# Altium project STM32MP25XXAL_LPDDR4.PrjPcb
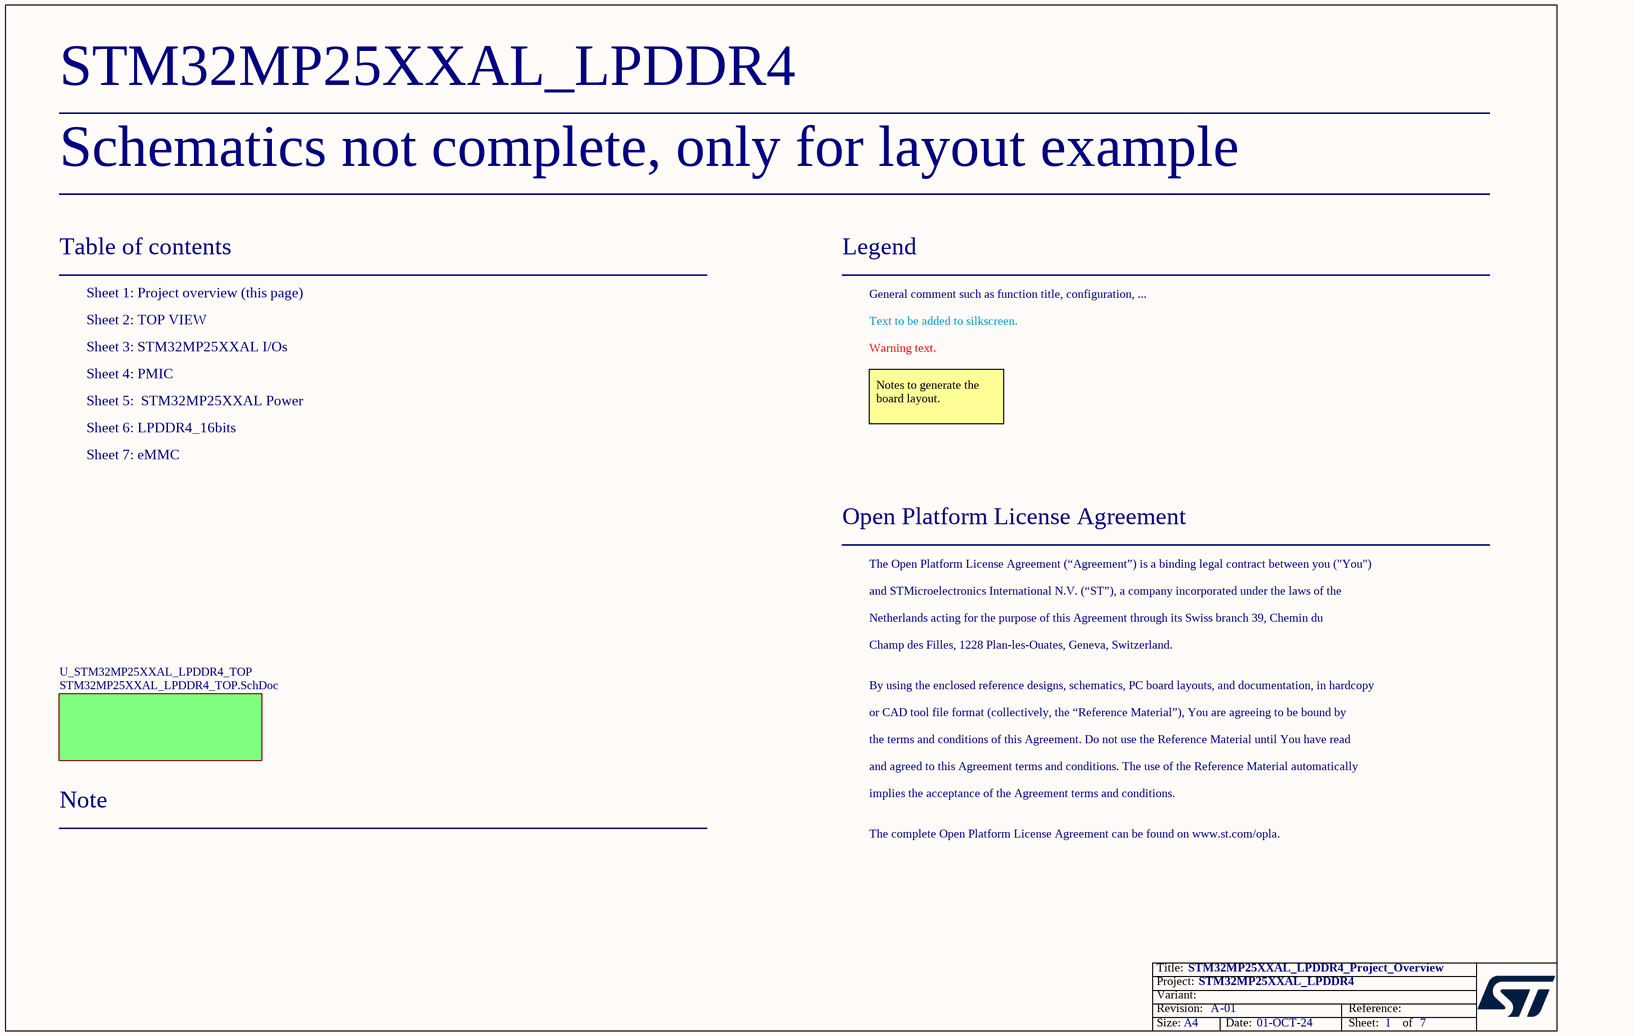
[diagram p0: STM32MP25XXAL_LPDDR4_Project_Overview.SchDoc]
Board_Assembly_Revision: 01; Board_Document_Date: 01-OCT-24; Board_Name: STM32MP25XXAL_LPDDR4; Board_PCB_Revision: A
7 sheets, 182 parts. Net scope: flat (ports and power ports of the same name join across sheets).
Board file: STM32MP25XXAL_LPDDR4.PcbDoc
Sheets:
  STM32MP25XXAL_LPDDR4_Project_Overview.SchDoc
    U_STM32MP25XXAL_LPDDR4_TOP = STM32MP25XXAL_LPDDR4_TOP.SchDoc
      U_STM32MP25XXAL I_Os = STM32MP25XXAL I_Os.SchDoc
      U_PMIC = PMIC.SchDoc
      U_STM32MP25XXAL Power = STM32MP25XXAL Power.SchDoc
      U_eMMC = eMMC.SchDoc
      U_LPDDR4_16bits = LPDDR4_16bits.SchDoc

## Sheet STM32MP25XXAL_LPDDR4_Project_Overview.SchDoc: STM32MP25XXAL_LPDDR4_Project_Overview
size A4; Date: Not used; ApprovedBy: Not used; CheckedBy: Not used; Author: Not used; CompanyName: STMicroelectronics; DrawnBy: Not used; Engineer: Not used; Organization: Not used; Address1: Not used; Address2: Not used; Address3: Not used; Address4: Not used; DocumentNumber: 1; Revision: Not used; SheetNumber: 1; SheetTotal: 7

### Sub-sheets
U_STM32MP25XXAL_LPDDR4_TOP = STM32MP25XXAL_LPDDR4_TOP.SchDoc: no entries

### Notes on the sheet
- Schematics not complete, only for layout example
- Table of contents
- Sheet 1: Project overview (this page)
- Legend
- General comment such as function title, configuration, ...
- Sheet 2: TOP VIEW
- Sheet 3: STM32MP25XXAL I/Os
- Sheet 4: PMIC
- Text to be added to silkscreen.
- Warning text.
- Sheet 5:  STM32MP25XXAL Power
- Sheet 6: LPDDR4_16bits
- Notes to generate the board layout.
- Sheet 7: eMMC
- Open Platform License Agreement
- The Open Platform License Agreement (“Agreement”) is a binding legal contract between you ("You")
- and STMicroelectronics International N.V. (“ST”), a company incorporated under the laws of the
- Netherlands acting for the purpose of this Agreement through its Swiss branch 39, Chemin du
- Champ des Filles, 1228 Plan-les-Ouates, Geneva, Switzerland.
- By using the enclosed reference designs, schematics, PC board layouts, and documentation, in hardcopy
- or CAD tool file format (collectively, the “Reference Material”), You are agreeing to be bound by
- the terms and conditions of this Agreement. Do not use the Reference Material until You have read
- and agreed to this Agreement terms and conditions. The use of the Reference Material automatically
- Note
- implies the acceptance of the Agreement terms and conditions.
- The complete Open Platform License Agreement can be found on www.st.com/opla.

## Sheet STM32MP25XXAL_LPDDR4_TOP.SchDoc: TOP
size A4; Date: Not used; ApprovedBy: Not used; CheckedBy: Not used; Author: Not used; CompanyName: STMicroelectronics; DrawnBy: Not used; Engineer: Not used; Organization: Not used; Address1: Not used; Address2: Not used; Address3: Not used; Address4: Not used; DocumentNumber: 2; Revision: Not used; SheetNumber: 2; SheetTotal: 7
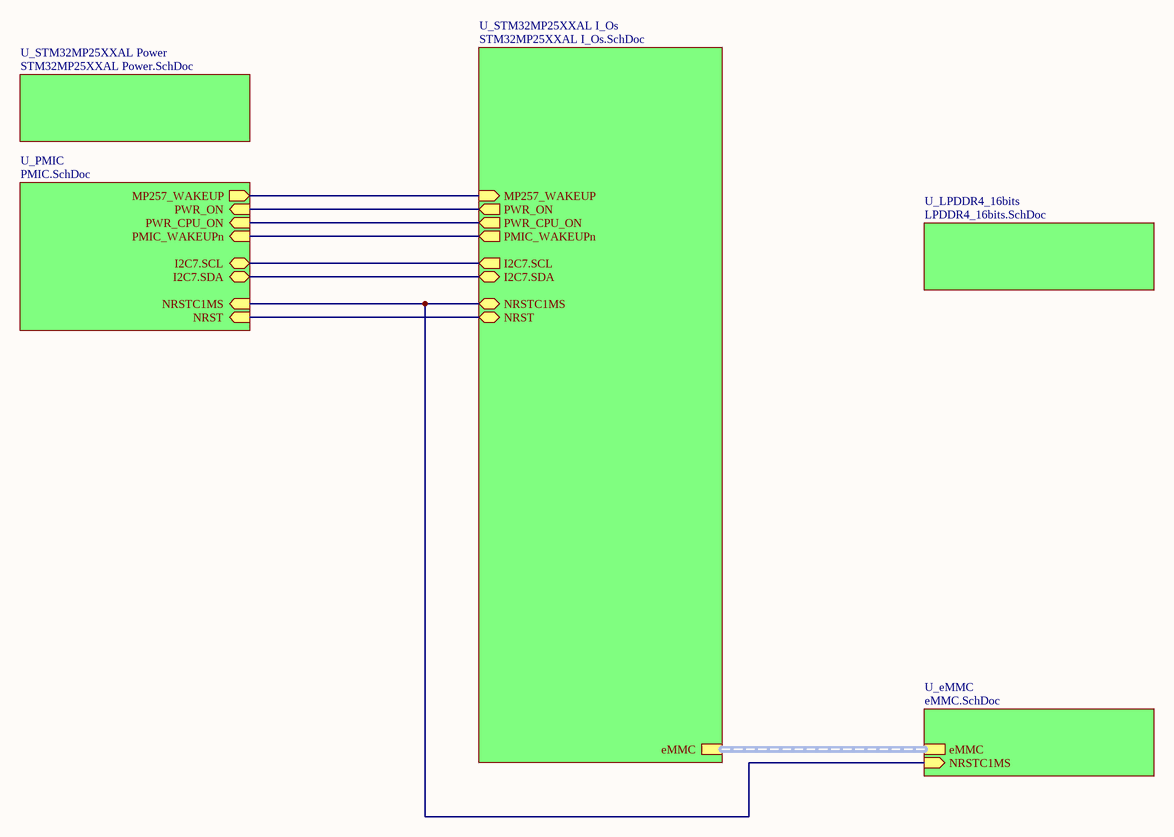
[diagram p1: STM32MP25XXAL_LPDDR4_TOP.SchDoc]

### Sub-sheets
U_eMMC = eMMC.SchDoc: eMMC (harness eMMC), NRSTC1MS (in)
U_LPDDR4_16bits = LPDDR4_16bits.SchDoc: no entries
U_PMIC = PMIC.SchDoc: PMIC_WAKEUPn (in), NRST (in), I2C7.SCL (bidir), PWR_ON (in), PWR_CPU_ON (in), NRSTC1MS (in), I2C7.SDA (bidir), MP257_WAKEUP (out)
U_STM32MP25XXAL I_Os = STM32MP25XXAL I_Os.SchDoc: NRST (bidir), PWR_ON (out), NRSTC1MS (bidir), I2C7.SDA (bidir), I2C7.SCL (out), PWR_CPU_ON (out), MP257_WAKEUP (in), PMIC_WAKEUPn (out), eMMC (harness eMMC)
U_STM32MP25XXAL Power = STM32MP25XXAL Power.SchDoc: no entries

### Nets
(unnamed): sheet U_STM32MP25XXAL I_Os/NRST, sheet U_PMIC/NRST
(unnamed): sheet U_STM32MP25XXAL I_Os/PWR_ON, sheet U_PMIC/PWR_ON  [a separate net that carries the same name]
(unnamed): sheet U_STM32MP25XXAL I_Os/NRSTC1MS, sheet U_PMIC/NRSTC1MS, sheet U_eMMC/NRSTC1MS  [a separate net that carries the same name]
(unnamed): sheet U_STM32MP25XXAL I_Os/I2C7.SDA, sheet U_PMIC/I2C7.SDA  [a separate net that carries the same name]
(unnamed): sheet U_STM32MP25XXAL I_Os/I2C7.SCL, sheet U_PMIC/I2C7.SCL  [a separate net that carries the same name]
(unnamed): sheet U_STM32MP25XXAL I_Os/PWR_CPU_ON, sheet U_PMIC/PWR_CPU_ON  [a separate net that carries the same name]
(unnamed): sheet U_STM32MP25XXAL I_Os/MP257_WAKEUP, sheet U_PMIC/MP257_WAKEUP  [a separate net that carries the same name]
(unnamed): sheet U_STM32MP25XXAL I_Os/PMIC_WAKEUPn, sheet U_PMIC/PMIC_WAKEUPn  [a separate net that carries the same name]

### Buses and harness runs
harness sheet U_eMMC/eMMC = sheet U_STM32MP25XXAL I_Os/eMMC

## Sheet STM32MP25XXAL I_Os.SchDoc: STM32MP25XXAL  I/Os
size A3; Date: Not used; ApprovedBy: Not used; CheckedBy: Not used; Author: Not used; CompanyName: STMicroelectronics; DrawnBy: Not used; Engineer: Not used; Organization: Not used; Address1: Not used; Address2: Not used; Address3: Not used; Address4: Not used; DocumentNumber: 3; Revision: Not used; SheetNumber: 3; SheetTotal: 7
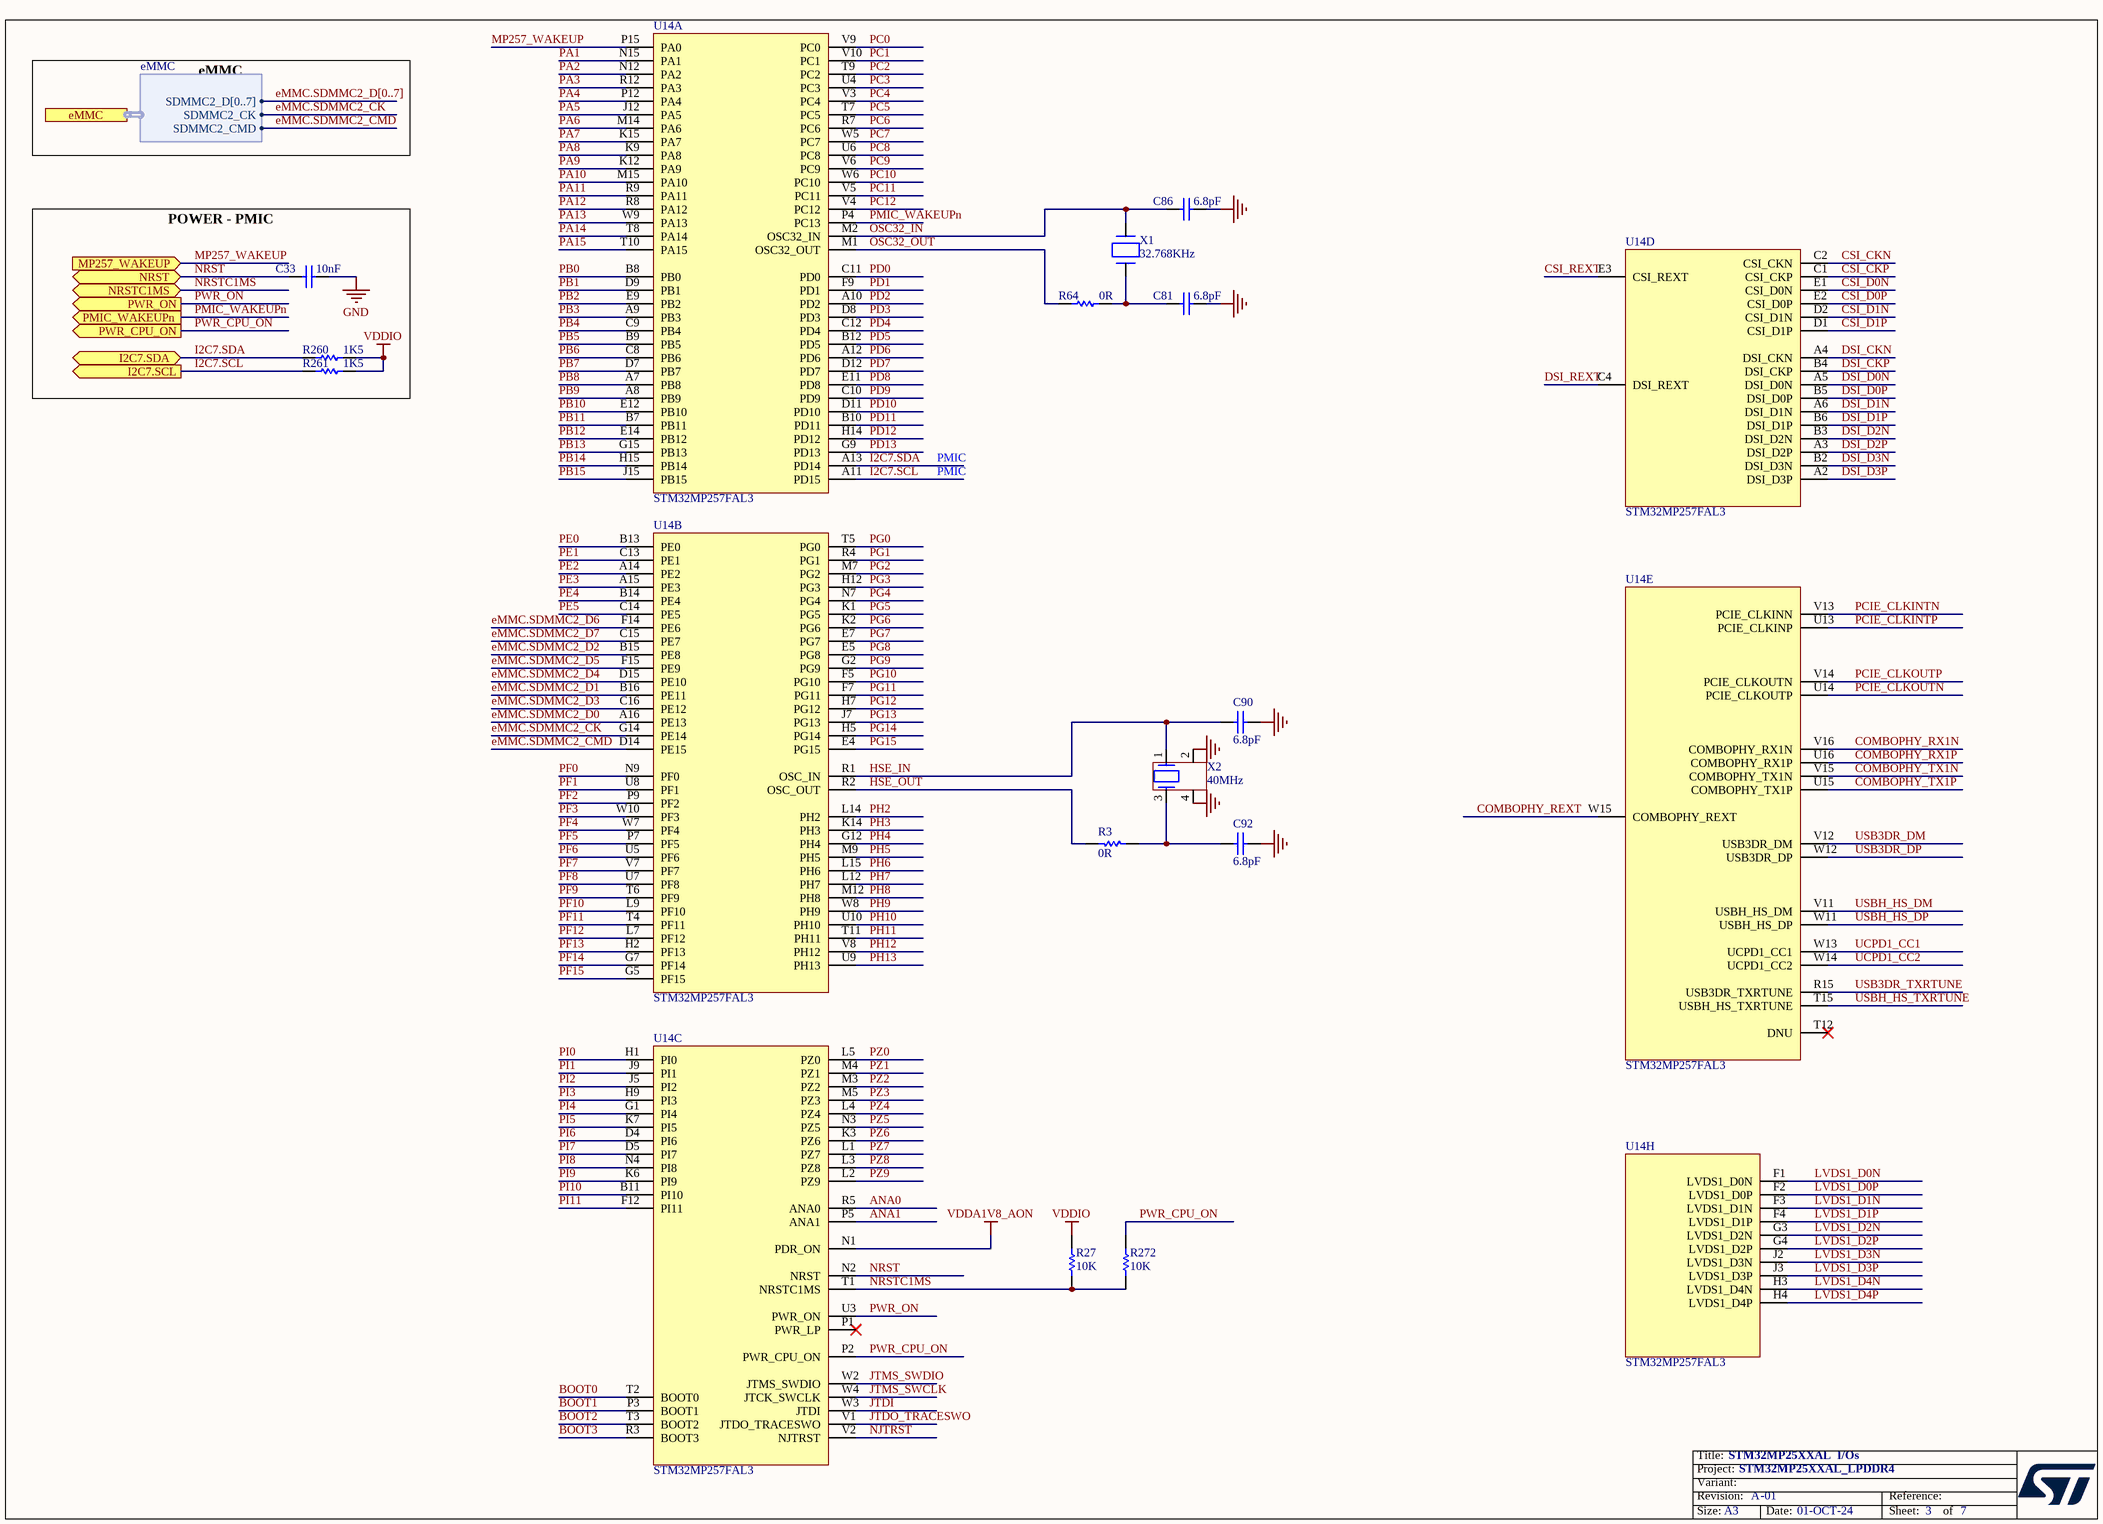
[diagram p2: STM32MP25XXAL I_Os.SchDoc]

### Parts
C33  value 10nF  [C0402]  (hidden comment: Capacitor)
C81  value 6.8pF  [C0402]  (hidden comment: Capacitor)
C86  value 6.8pF  [C0402]  (hidden comment: Capacitor)
C90  value 6.8pF  [C0402]  (hidden comment: Capacitor)
C92  value 6.8pF  [C0402]  (hidden comment: Capacitor)
R3  value 0R  [R0402]  (hidden comment: Resistor)
R27  value 10K  [R0402]  (hidden comment: Resistor)
R64  value 0R  [R0402]  (hidden comment: Resistor)
R260  value 1K5  [R0402]  (hidden comment: Resistor)
R261  value 1K5  [R0402]  (hidden comment: Resistor)
R272  value 10K  [R0402]  (hidden comment: Resistor)
U14  STM32MP257FAL3  [ICC_VFBGA361_10X10_P050]  (parts A,B,C,D,E,H of 8)
X1  value 32.768KHz  [CRY_NX2012SA_2P]  (hidden comment: XTAL_2_PINS)
X2  value 40MHz  [CRY_NX1612SA_4P]  (hidden comment: XTAL_4_PINS)

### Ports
eMMC (harness eMMC), I2C7.SCL (out), I2C7.SDA (bidir), MP257_WAKEUP (in), NRST (bidir), NRSTC1MS (bidir), PMIC_WAKEUPn (out), PWR_CPU_ON (out), PWR_ON (out)

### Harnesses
eMMC: SDMMC2_CK, SDMMC2_CMD, SDMMC2_D[0..7]

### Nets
GND: C33.1 C81.2 C86.2 C90.1 C92.2 X2.2 X2.4
VDDA1V8_AON: U14.N1(PDR_ON)
VDDIO: R27.2 R260.2 R261.2
ANA0: U14.R5(ANA0)
ANA1: U14.P5(ANA1)
BOOT0: U14.T2(BOOT0)
BOOT1: U14.P3(BOOT1)
BOOT2: U14.T3(BOOT2)
BOOT3: U14.R3(BOOT3)
COMBOPHY_REXT: U14.W15(COMBOPHY_REXT)
COMBOPHY_RX1N: U14.V16(COMBOPHY_RX1N)
COMBOPHY_RX1P: U14.U16(COMBOPHY_RX1P)
COMBOPHY_TX1N: U14.V15(COMBOPHY_TX1N)
COMBOPHY_TX1P: U14.U15(COMBOPHY_TX1P)
CSI_CKN: U14.C2(CSI_CKN)
CSI_CKP: U14.C1(CSI_CKP)
CSI_D0N: U14.E1(CSI_D0N)
CSI_D0P: U14.E2(CSI_D0P)
CSI_D1N: U14.D2(CSI_D1N)
CSI_D1P: U14.D1(CSI_D1P)
CSI_REXT: U14.E3(CSI_REXT)
DSI_CKN: U14.A4(DSI_CKN)
DSI_CKP: U14.B4(DSI_CKP)
DSI_D0N: U14.A5(DSI_D0N)
DSI_D0P: U14.B5(DSI_D0P)
DSI_D1N: U14.A6(DSI_D1N)
DSI_D1P: U14.B6(DSI_D1P)
DSI_D2N: U14.B3(DSI_D2N)
DSI_D2P: U14.A3(DSI_D2P)
DSI_D3N: U14.B2(DSI_D3N)
DSI_D3P: U14.A2(DSI_D3P)
DSI_REXT: U14.C4(DSI_REXT)
eMMC.SDMMC2_CK: U14.G14(PE14) ; port eMMC.SDMMC2_CK
eMMC.SDMMC2_CMD: U14.D14(PE15) ; port eMMC.SDMMC2_CMD
eMMC.SDMMC2_D0: U14.A16(PE13)
eMMC.SDMMC2_D1: U14.B16(PE11)
eMMC.SDMMC2_D2: U14.B15(PE8)
eMMC.SDMMC2_D3: U14.C16(PE12)
eMMC.SDMMC2_D4: U14.D15(PE10)
eMMC.SDMMC2_D5: U14.F15(PE9)
eMMC.SDMMC2_D6: U14.F14(PE6)
eMMC.SDMMC2_D7: U14.C15(PE7)
HSE_IN: C90.2 U14.R1(OSC_IN) X2.1
HSE_OUT: R3.2 U14.R2(OSC_OUT)
I2C7.SCL: R261.1 U14.A11(PD15) ; port I2C7.SCL
I2C7.SDA: R260.1 U14.A13(PD14) ; port I2C7.SDA
JTDI: U14.W3(JTDI)
JTDO_TRACESWO: U14.V1(JTDO_TRACESWO)
JTMS_SWCLK: U14.W4(JTCK_SWCLK)
JTMS_SWDIO: U14.W2(JTMS_SWDIO)
LVDS1_D0N: U14.F1(LVDS1_D0N)
LVDS1_D0P: U14.F2(LVDS1_D0P)
LVDS1_D1N: U14.F3(LVDS1_D1N)
LVDS1_D1P: U14.F4(LVDS1_D1P)
LVDS1_D2N: U14.G3(LVDS1_D2N)
LVDS1_D2P: U14.G4(LVDS1_D2P)
LVDS1_D3N: U14.J2(LVDS1_D3N)
LVDS1_D3P: U14.J3(LVDS1_D3P)
LVDS1_D4N: U14.H3(LVDS1_D4N)
LVDS1_D4P: U14.H4(LVDS1_D4P)
MP257_WAKEUP: U14.P15(PA0) ; port MP257_WAKEUP
NJTRST: U14.V2(NJTRST)
NRST: C33.2 U14.N2(NRST) ; port NRST
NRSTC1MS: R27.1 R272.1 U14.T1(NRSTC1MS) ; port NRSTC1MS
OSC32_IN: C86.1 U14.M2(OSC32_IN) X1.2(X2)
OSC32_OUT: R64.1 U14.M1(OSC32_OUT)
PA1: U14.N15(PA1)
PA2: U14.N12(PA2)
PA3: U14.R12(PA3)
PA4: U14.P12(PA4)
PA5: U14.J12(PA5)
PA6: U14.M14(PA6)
PA7: U14.K15(PA7)
PA8: U14.K9(PA8)
PA9: U14.K12(PA9)
PA10: U14.M15(PA10)
PA11: U14.R9(PA11)
PA12: U14.R8(PA12)
PA13: U14.W9(PA13)
PA14: U14.T8(PA14)
PA15: U14.T10(PA15)
PB0: U14.B8(PB0)
PB1: U14.D9(PB1)
PB2: U14.E9(PB2)
PB3: U14.A9(PB3)
PB4: U14.C9(PB4)
PB5: U14.B9(PB5)
PB6: U14.C8(PB6)
PB7: U14.D7(PB7)
PB8: U14.A7(PB8)
PB9: U14.A8(PB9)
PB10: U14.E12(PB10)
PB11: U14.B7(PB11)
PB12: U14.E14(PB12)
PB13: U14.G15(PB13)
PB14: U14.H15(PB14)
PB15: U14.J15(PB15)
PC0: U14.V9(PC0)
PC1: U14.V10(PC1)
PC2: U14.T9(PC2)
PC3: U14.U4(PC3)
PC4: U14.V3(PC4)
PC5: U14.T7(PC5)
PC6: U14.R7(PC6)
PC7: U14.W5(PC7)
PC8: U14.U6(PC8)
PC9: U14.V6(PC9)
PC10: U14.W6(PC10)
PC11: U14.V5(PC11)
PC12: U14.V4(PC12)
PCIE_CLKINTN: U14.V13(PCIE_CLKINN)
PCIE_CLKINTP: U14.U13(PCIE_CLKINP)
PCIE_CLKOUTN: U14.U14(PCIE_CLKOUTP)
PCIE_CLKOUTP: U14.V14(PCIE_CLKOUTN)
PD0: U14.C11(PD0)
PD1: U14.F9(PD1)
PD2: U14.A10(PD2)
PD3: U14.D8(PD3)
PD4: U14.C12(PD4)
PD5: U14.B12(PD5)
PD6: U14.A12(PD6)
PD7: U14.D12(PD7)
PD8: U14.E11(PD8)
PD9: U14.C10(PD9)
PD10: U14.D11(PD10)
PD11: U14.B10(PD11)
PD12: U14.H14(PD12)
PD13: U14.G9(PD13)
PE0: U14.B13(PE0)
PE1: U14.C13(PE1)
PE2: U14.A14(PE2)
PE3: U14.A15(PE3)
PE4: U14.B14(PE4)
PE5: U14.C14(PE5)
PF0: U14.N9(PF0)
PF1: U14.U8(PF1)
PF2: U14.P9(PF2)
PF3: U14.W10(PF3)
PF4: U14.W7(PF4)
PF5: U14.P7(PF5)
PF6: U14.U5(PF6)
PF7: U14.V7(PF7)
PF8: U14.U7(PF8)
PF9: U14.T6(PF9)
PF10: U14.L9(PF10)
PF11: U14.T4(PF11)
PF12: U14.L7(PF12)
PF13: U14.H2(PF13)
PF14: U14.G7(PF14)
PF15: U14.G5(PF15)
PG0: U14.T5(PG0)
PG1: U14.R4(PG1)
PG2: U14.M7(PG2)
PG3: U14.H12(PG3)
PG4: U14.N7(PG4)
PG5: U14.K1(PG5)
PG6: U14.K2(PG6)
PG7: U14.E7(PG7)
PG8: U14.E5(PG8)
PG9: U14.G2(PG9)
PG10: U14.F5(PG10)
PG11: U14.F7(PG11)
PG12: U14.H7(PG12)
PG13: U14.J7(PG13)
PG14: U14.H5(PG14)
PG15: U14.E4(PG15)
PH2: U14.L14(PH2)
PH3: U14.K14(PH3)
PH4: U14.G12(PH4)
PH5: U14.M9(PH5)
PH6: U14.L15(PH6)
PH7: U14.L12(PH7)
PH8: U14.M12(PH8)
PH9: U14.W8(PH9)
PH10: U14.U10(PH10)
PH11: U14.T11(PH11)
PH12: U14.V8(PH12)
PH13: U14.U9(PH13)
PI0: U14.H1(PI0)
PI1: U14.J9(PI1)
PI2: U14.J5(PI2)
PI3: U14.H9(PI3)
PI4: U14.G1(PI4)
PI5: U14.K7(PI5)
PI6: U14.D4(PI6)
PI7: U14.D5(PI7)
PI8: U14.N4(PI8)
PI9: U14.K6(PI9)
PI10: U14.B11(PI10)
PI11: U14.F12(PI11)
PMIC_WAKEUPn: U14.P4(PC13) ; port PMIC_WAKEUPn
PWR_CPU_ON: R272.2 U14.P2(PWR_CPU_ON) ; port PWR_CPU_ON
PWR_ON: U14.U3(PWR_ON) ; port PWR_ON
PZ0: U14.L5(PZ0)
PZ1: U14.M4(PZ1)
PZ2: U14.M3(PZ2)
PZ3: U14.M5(PZ3)
PZ4: U14.L4(PZ4)
PZ5: U14.N3(PZ5)
PZ6: U14.K3(PZ6)
PZ7: U14.L1(PZ7)
PZ8: U14.L3(PZ8)
PZ9: U14.L2(PZ9)
UCPD1_CC1: U14.W13(UCPD1_CC1)
UCPD1_CC2: U14.W14(UCPD1_CC2)
USB3DR_DM: U14.V12(USB3DR_DM)
USB3DR_DP: U14.W12(USB3DR_DP)
USB3DR_TXRTUNE: U14.R15(USB3DR_TXRTUNE)
USBH_HS_DM: U14.V11(USBH_HS_DM)
USBH_HS_DP: U14.W11(USBH_HS_DP)
USBH_HS_TXRTUNE: U14.T15(USBH_HS_TXRTUNE)
NetC81_1: C81.1 R64.2 X1.1(X1)
NetC92_1: C92.1 R3.1 X2.3

Not connected (* = marked no-connect by the designer): U14 P1(PWR_LP)* T12(DNU)*

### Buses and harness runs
bus eMMC.SDMMC2_D[0..7]

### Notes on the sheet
- eMMC
- POWER - PMIC
- PMIC

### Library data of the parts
C33 = MCD-00011: Capacitor, MLCC, 10nF, 16V, X7R, +/-10%, 0402, T=0.5mm; Manufacturer_Part_Number: CC0402KRX7R7BB103; Manufacturer: YAGEO; Part_Preference: Recommended; Order_Code_RS: 3019275; Component_Country_Of_Origin: China; ShowFields: YES; ID: 2469
C81 C86 C90 C92 = MCD-00674: Capacitor, MLCC, 6.8pF, 50V, NPO, +/-0.25pF, 0402, T=0.5mm; Manufacturer_Part_Number: CC0402CRNPO9BN6R8; Manufacturer: YAGEO; Part_Preference: Recommended; Component_Country_Of_Origin: China; ID: 3068; ShowFields: YES
R3 R64 = MCD-00052: Resistor, 0R, 0402, +/-5%, 1/16W; Manufacturer_Part_Number: RC0402JR-070RL; Manufacturer: YAGEO; Part_Preference: Recommended; Order_Code_RS: 9232516RL; Component_Country_Of_Origin: China; ID: 2540; ShowFields: YES
R27 R272 = MCD-00053: Resistor, 10K, 0402, +/-1%, 1/16W; BMS_Part_Number: 9131590; Part_Preference: Recommended; Manufacturer: YAGEO; Manufacturer_Part_Number: RC0402FR-0710KL; Order_Code_RS: 9239359; Component_Country_Of_Origin: China; ID: 2539; ShowFields: YES
R260 R261 = MCD-00068: Resistor, 1K5, 0402, +/-1%, 1/16W; Part_Preference: Recommended; Manufacturer: YAGEO; Manufacturer_Part_Number: RC0402FR-071K5L; Order_Code_RS: 9239251; Component_Country_Of_Origin: China; ID: 2524; ShowFields: YES
U14 = MCD-03768: MPU, dual core ARM cortex-A35 64-bit + M33 32-bit, 808KB SRAM, With Crypto; Part_Type: IC; Part_Preference: Recommended; Manufacturer: STMICROELECTRONICS; Component_Country_Of_Origin: Unknown; ShowFields: YES; ID: 5884
X1 = MCD-01479: Crystal, 32.768kHz, 6pF, +/-20ppm, 80K, 2.05x1.2mm; BMS_Part_Number: 9157049; Part_Type: Crystal_Osc; Part_Preference: Recommended; Manufacturer: NDK; Manufacturer_Part_Number: NX2012SA-32.768KHZ-EXS00A-MU00527; Component_Country_Of_Origin: Unknown; ShowFields: YES; ID: 3579
X2 = MCD-02344: Crystal, 40MHz, 6pF, +/-20ppm, 80R, 1.6x1.2mm; Part_Type: Crystal_Osc; Part_Preference: Not recommended; Manufacturer: NDK; Manufacturer_Part_Number: NX1612SA-40MHZ-EXS00A-CS13836; Component_Country_Of_Origin: Unknown; ShowFields: YES; ID: 4450

## Sheet PMIC.SchDoc: PMIC
size A3; Date: Not used; ApprovedBy: Not used; CheckedBy: Not used; Author: Not used; CompanyName: STMicroelectronics; DrawnBy: Not used; Engineer: Not used; Organization: Not used; Address1: Not used; Address2: Not used; Address3: Not used; Address4: Not used; DocumentNumber: 4; Revision: Not used; SheetNumber: 4; SheetTotal: 7
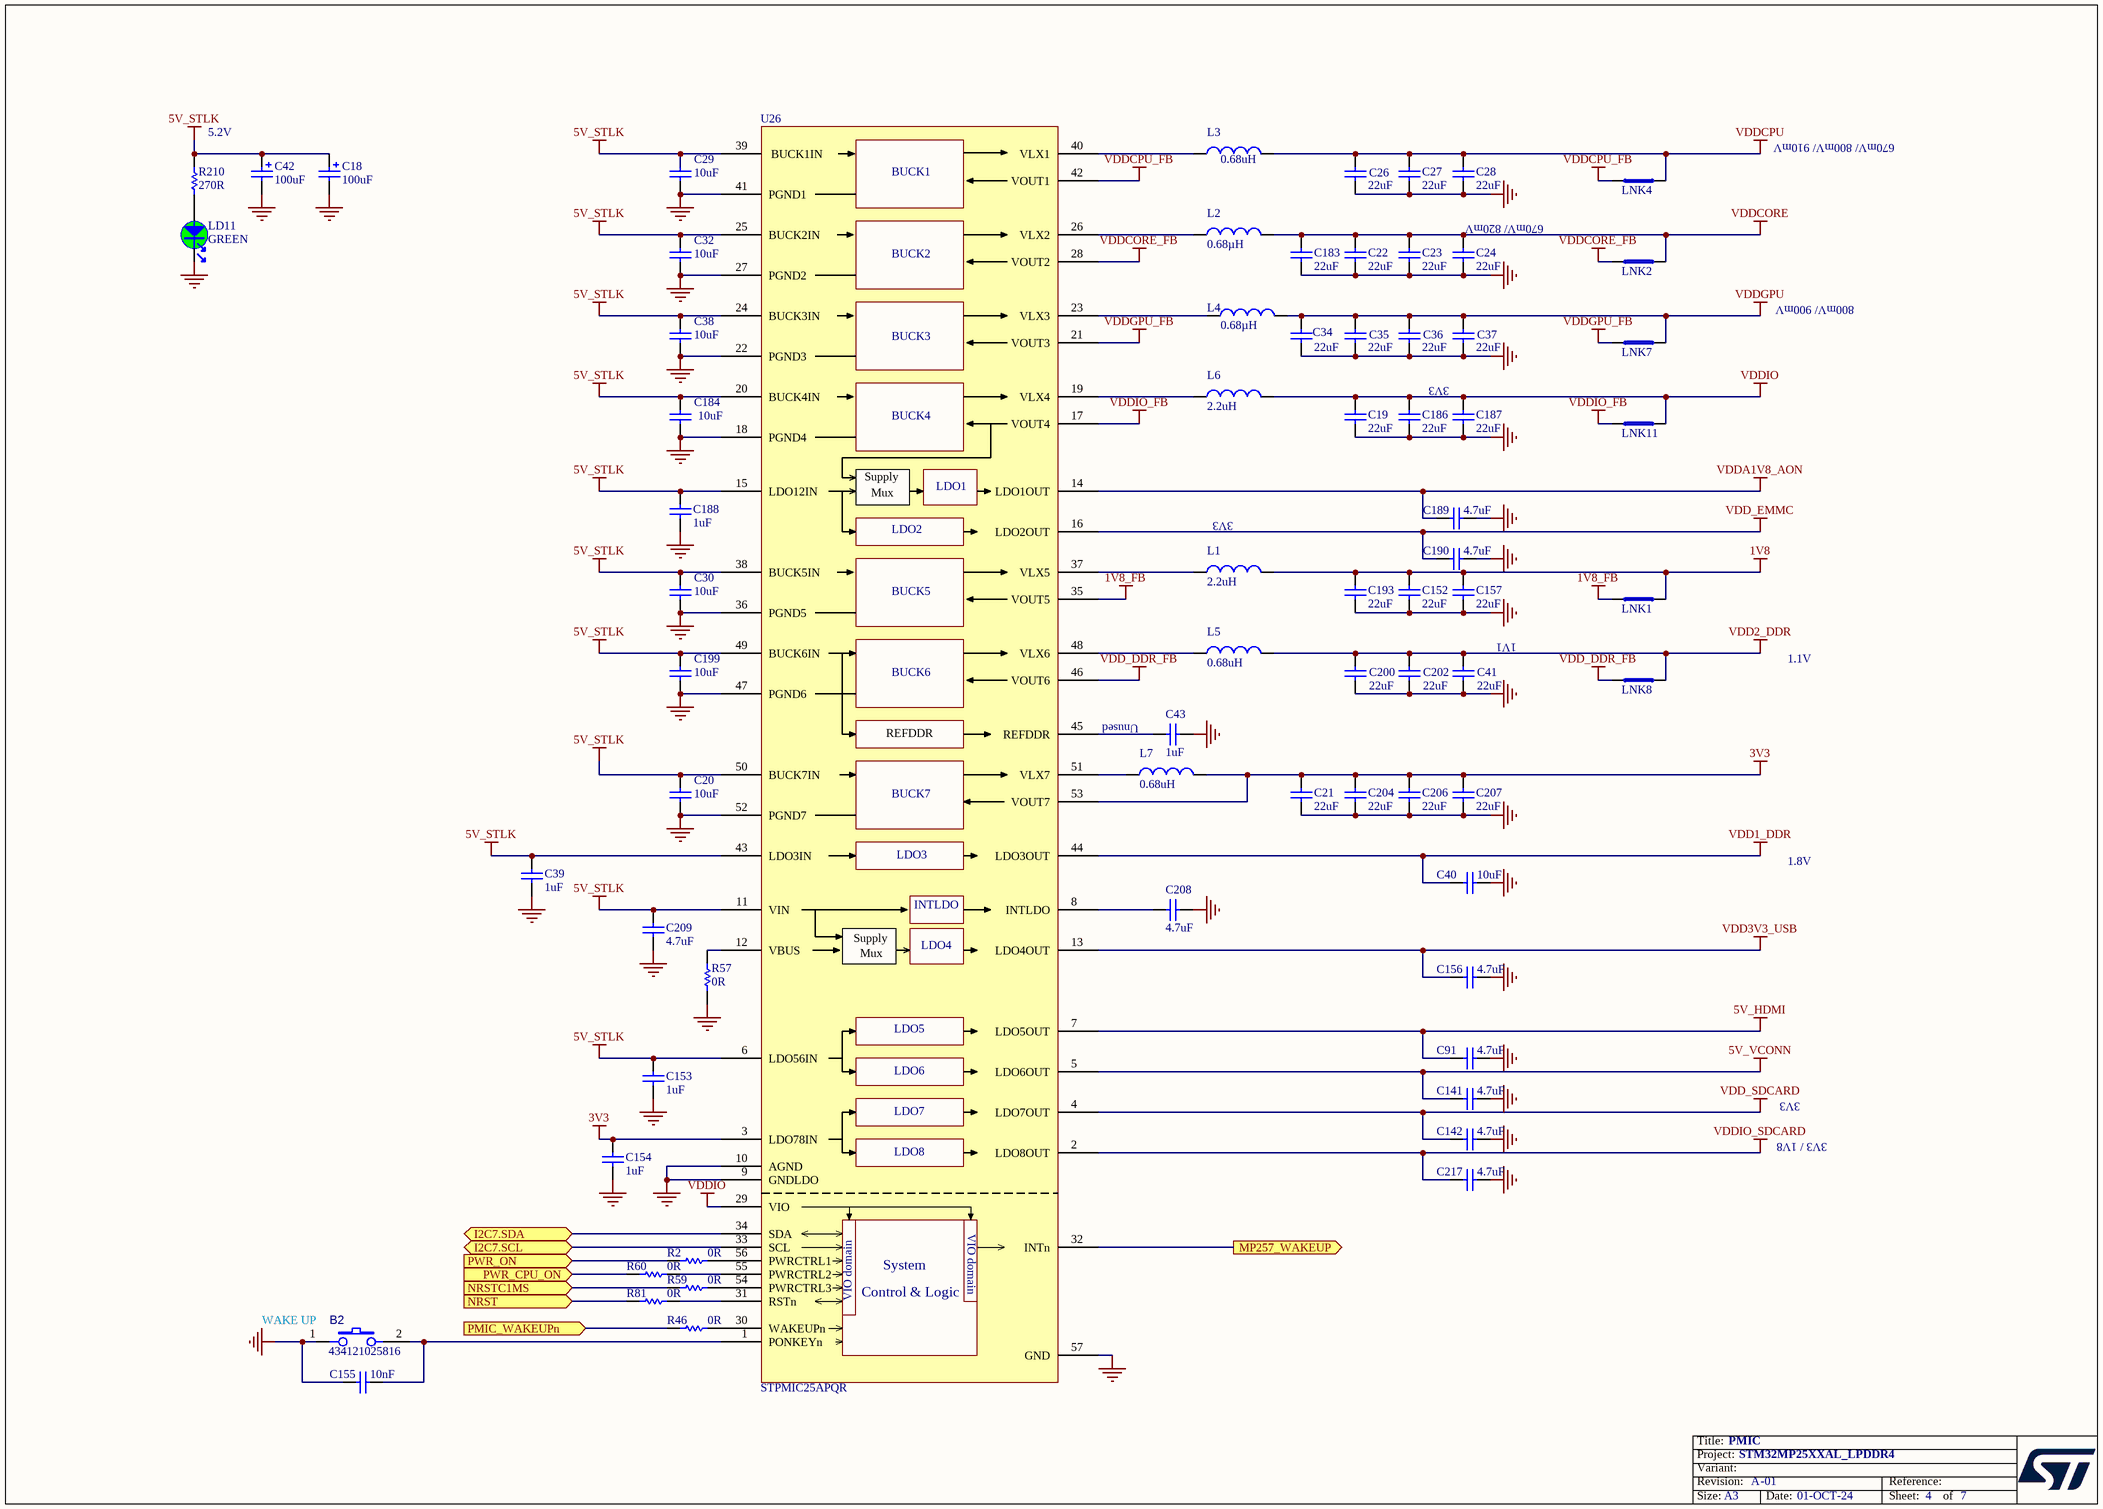
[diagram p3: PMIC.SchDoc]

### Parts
B2  value 434121025816  [SWI_WE_434121025816]  (hidden comment: SW_PUSH_SMD_2P)
C18  value 100uF  [CPOL_TCJ-B_1210_H210]  (hidden comment: Cap_POL_TANA)
C19  value 22uF  [C0805]  (hidden comment: Capacitor)
C20  value 10uF  [C0603]  (hidden comment: Capacitor)
C21  value 22uF  [C0805]  (hidden comment: Capacitor)
C22  value 22uF  [C0603]  (hidden comment: Capacitor)
C23  value 22uF  [C0603]  (hidden comment: Capacitor)
C24  value 22uF  [C0603]  (hidden comment: Capacitor)
C26  value 22uF  [C0603]  (hidden comment: Capacitor)
C27  value 22uF  [C0603]  (hidden comment: Capacitor)
C28  value 22uF  [C0603]  (hidden comment: Capacitor)
C29  value 10uF  [C0603]  (hidden comment: Capacitor)
C30  value 10uF  [C0603]  (hidden comment: Capacitor)
C32  value 10uF  [C0603]  (hidden comment: Capacitor)
C34  value 22uF  [C0603]  (hidden comment: Capacitor)
C35  value 22uF  [C0603]  (hidden comment: Capacitor)
C36  value 22uF  [C0603]  (hidden comment: Capacitor)
C37  value 22uF  [C0603]  (hidden comment: Capacitor)
C38  value 10uF  [C0603]  (hidden comment: Capacitor)
C39  value 1uF  [C0402]  (hidden comment: Capacitor)
C40  value 10uF  [C0402]  (hidden comment: Capacitor)
C41  value 22uF  [C0603]  (hidden comment: Capacitor)
C42  value 100uF  [CPOL_TCJ-B_1210_H210]  (hidden comment: Cap_POL_TANA)
C43  value 1uF  [C0402]  (hidden comment: Capacitor)
C91  value 4.7uF  [C0402]  (hidden comment: Capacitor)
C141  value 4.7uF  [C0402]  (hidden comment: Capacitor)
C142  value 4.7uF  [C0402]  (hidden comment: Capacitor)
C152  value 22uF  [C0805]  (hidden comment: Capacitor)
C153  value 1uF  [C0402]  (hidden comment: Capacitor)
C154  value 1uF  [C0402]  (hidden comment: Capacitor)
C155  value 10nF  [C0402]  (hidden comment: Capacitor)
C156  value 4.7uF  [C0402]  (hidden comment: Capacitor)
C157  value 22uF  [C0805]  (hidden comment: Capacitor)
C183  value 22uF  [C0603]  (hidden comment: Capacitor)
C184  value 10uF  [C0603]  (hidden comment: Capacitor)
C186  value 22uF  [C0805]  (hidden comment: Capacitor)
C187  value 22uF  [C0805]  (hidden comment: Capacitor)
C188  value 1uF  [C0402]  (hidden comment: Capacitor)
C189  value 4.7uF  [C0402]  (hidden comment: Capacitor)
C190  value 4.7uF  [C0402]  (hidden comment: Capacitor)
C193  value 22uF  [C0805]  (hidden comment: Capacitor)
C199  value 10uF  [C0603]  (hidden comment: Capacitor)
C200  value 22uF  [C0603]  (hidden comment: Capacitor)
C202  value 22uF  [C0603]  (hidden comment: Capacitor)
C204  value 22uF  [C0805]  (hidden comment: Capacitor)
C206  value 22uF  [C0805]  (hidden comment: Capacitor)
C207  value 22uF  [C0805]  (hidden comment: Capacitor)
C208  value 4.7uF  [C0402]  (hidden comment: Capacitor)
C209  value 4.7uF  [C0402]  (hidden comment: Capacitor)
C217  value 4.7uF  [C0402]  (hidden comment: Capacitor)
L1  value 2.2uH  [IND_2016_MURATA_LQM2MPN2R2NG0]  (hidden comment: Inductor)
L2  value 0.68µH  [IND_2520_TOKO_DFE252012P]  (hidden comment: Inductor)
L3  value 0.68uH  [IND_2016_MURATA_LQM2MPN2R2NG0]  (hidden comment: Inductor)
L4  value 0.68µH  [IND_2520_TOKO_DFE252012P]  (hidden comment: Inductor)
L5  value 0.68uH  [IND_2016_MURATA_LQM2MPN2R2NG0]  (hidden comment: Inductor)
L6  value 2.2uH  [IND_2016_MURATA_LQM2MPN2R2NG0]  (hidden comment: Inductor)
L7  value 0.68uH  [IND_2016_MURATA_LQM2MPN2R2NG0]  (hidden comment: Inductor)
LD11  value GREEN  [LED_0603_OSRAM_LG-Q396-PS-35_GREEN_1A2K_H0P4]  (hidden comment: LED_green)
LNK1  link_200  [LINK200]  (value not drawn)  (no BOM)
LNK2  link_200  [LINK200]  (value not drawn)  (no BOM)
LNK4  link_200  [LINK200]  (value not drawn)  (no BOM)
LNK7  link_200  [LINK200]  (value not drawn)  (no BOM)
LNK8  link_200  [LINK200]  (value not drawn)  (no BOM)
LNK11  link_200  [LINK200]  (value not drawn)  (no BOM)
R2  value 0R  [R0402]
R46  value 0R  [R0402]
R57  value 0R  [R0402]
R59  value 0R  [R0402]
R60  value 0R  [R0402]
R81  value 0R  [R0402]
R210  value 270R  [R0402]  (hidden comment: Resistor)
U26  STPMIC25APQR  [ICC_QFN56-EPAD_6P5X6P5_P040]

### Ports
I2C7.SCL (bidir), I2C7.SDA (bidir), MP257_WAKEUP (out), NRST (in), NRSTC1MS (in), PMIC_WAKEUPn (in), PWR_CPU_ON (in), PWR_ON (in)

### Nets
1V8: C152.2 C157.2 C193.2 L1.2 LNK1.2
1V8_FB: LNK1.1 U26.35(VOUT5)
3V3: C21.2 C154.2 C204.2 C206.2 C207.2 L7.2 U26.3(LDO78IN) U26.53(VOUT7)
5V_HDMI: C91.1 U26.7(LDO5OUT)
5V_STLK: C18.1 C20.2 C29.2 C30.2 C32.2 C38.2 C39.2 C42.1 C153.2 C184.2 C188.2 C199.2 C209.2 R210.1 U26.6(LDO56IN) U26.11(VIN) U26.15(LDO12IN) U26.20(BUCK4IN) U26.24(BUCK3IN) U26.25(BUCK2IN) U26.38(BUCK5IN) U26.39(BUCK1IN) U26.43(LDO3IN) U26.49(BUCK6IN) U26.50(BUCK7IN)
5V_VCONN: C141.1 U26.5(LDO6OUT)
GND: B2.1 C18.2 C19.1 C20.1 C21.1 C22.1 C23.1 C24.1 C26.1 C27.1 C28.1 C29.1 C30.1 C32.1 C34.1 C35.1 C36.1 C37.1 C38.1 C39.1 C40.1 C41.1 C42.2 C43.1 C91.2 C141.2 C142.2 C152.1 C153.1 C154.1 C155.1 C156.1 C157.1 C183.1 C184.1 C186.1 C187.1 C188.1 C189.1 C190.2 C193.1 C199.1 C200.1 C202.1 C204.1 C206.1 C207.1 C208.2 C209.1 C217.2 LD11.2 R57.1 U26.9(GNDLDO) U26.10(AGND) U26.18(PGND4) U26.22(PGND3) U26.27(PGND2) U26.36(PGND5) U26.41(PGND1) U26.47(PGND6) U26.52(PGND7) U26.57(GND)
VDD1_DDR: C40.2 U26.44(LDO3OUT)
VDD2_DDR: C41.2 C200.2 C202.2 L5.2 LNK8.2
VDD3V3_USB: C156.2 U26.13(LDO4OUT)
VDD_DDR_FB: LNK8.1 U26.46(VOUT6)
VDD_EMMC: C190.1 U26.16(LDO2OUT)
VDD_SDCARD: C142.1 U26.4(LDO7OUT)
VDDA1V8_AON: C189.2 U26.14(LDO1OUT)
VDDCORE: C22.2 C23.2 C24.2 C183.2 L2.2 LNK2.2
VDDCORE_FB: LNK2.1 U26.28(VOUT2)
VDDCPU: C26.2 C27.2 C28.2 L3.2 LNK4.1
VDDCPU_FB: LNK4.2 U26.42(VOUT1)
VDDGPU: C34.2 C35.2 C36.2 C37.2 L4.2 LNK7.2
VDDGPU_FB: LNK7.1 U26.21(VOUT3)
VDDIO: C19.2 C186.2 C187.2 L6.2 LNK11.2 U26.29(VIO)
VDDIO_FB: LNK11.1 U26.17(VOUT4)
VDDIO_SDCARD: C217.1 U26.2(LDO8OUT)
I2C7.SCL: U26.33(SCL) ; port I2C7.SCL
I2C7.SDA: U26.34(SDA) ; port I2C7.SDA
MP257_WAKEUP: U26.32(INTn) ; port MP257_WAKEUP
NRST: R81.1 ; port NRST
NRSTC1MS: R59.1 ; port NRSTC1MS
PMIC_WAKEUPn: R46.1 ; port PMIC_WAKEUPn
PWR_CPU_ON: R60.1 ; port PWR_CPU_ON
PWR_ON: R2.1 ; port PWR_ON
NetB2_2: B2.2 C155.2 U26.1(PONKEYn)
NetC43_2: C43.2 U26.45(REFDDR)
NetC208_1: C208.1 U26.8(INTLDO)
NetL1_1: L1.1 U26.37(VLX5)
NetL2_1: L2.1 U26.26(VLX2)
NetL3_1: L3.1 U26.40(VLX1)
NetL4_1: L4.1 U26.23(VLX3)
NetL5_1: L5.1 U26.48(VLX6)
NetL6_1: L6.1 U26.19(VLX4)
NetL7_1: L7.1 U26.51(VLX7)
NetLD11_1: LD11.1 R210.2
NetR2_2: R2.2 U26.56(PWRCTRL1)
NetR46_2: R46.2 U26.30(WAKEUPn)
NetR57_2: R57.2 U26.12(VBUS)
NetR59_2: R59.2 U26.54(PWRCTRL3)
NetR60_2: R60.2 U26.55(PWRCTRL2)
NetR81_2: R81.2 U26.31(RSTn)

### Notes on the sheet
- 5.2V
- 670mV/ 800mV/ 910mV
- (near C24) 670mV/ 820mV
- 800mV/ 900mV
- 3V3
- (near L1) 3V3
- 1V1
- Unused
- 1.1V
- 1.8V
- 3V3 / 1V8
- (near B2) WAKE UP

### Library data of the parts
B2 = MCD-03492: Switch tactile, SPST-NO, 50mA, 12V, 6x3.8mm; Part_Type: Misc; Part_Preference: Recommended; Manufacturer: WURTH ELEKTRONIC; Component_Country_Of_Origin: China°; ShowFields: YES; ID: 5608
C18 C42 = MCD-01796: Capacitor, Tantalum, 100uF, 6V3, 40mR, +/-20%,  Type_B (3528 metric), T=1.9mm; Part_Preference: Recommended; Manufacturer: AVX; Manufacturer_Part_Number: TCJB107M006R0040; Component_Country_Of_Origin: Lanskroun; ShowFields: YES; ID: 3896
C19 C21 C152 C157 C186 C187 C193 C204 C206 C207 = MCD-03139: Capacitor, MLCC, 22uF, 10V, X5R, +/-20%, 0805, T=1,25mm; Part_Preference: Recommended; Manufacturer: MURATA; Manufacturer_Part_Number: GRM21BR61A226ME51L; ShowFields: YES; ID: 5255; Component_Country_Of_Origin: China, Japan
C20 C29 C30 C32 C38 C184 C199 = MCD-00099: Capacitor, MLCC, 10uF, 10V, X5R, +/-10%, 0603, T=0,8mm; Manufacturer_Part_Number: GRM188R61A106KE69D; Manufacturer: MURATA; Part_Preference: Recommended; Order_Code_RS: 170-6168; Component_Country_Of_Origin: Japan; ID: 2770; ShowFields: YES
C22-C24 C26 C34-C37 C41 C200 C202 = MCD-00100: Capacitor, MLCC, 22uF, 6V3, X5R, +/-20%, 0603, T=0,8mm; Manufacturer_Part_Number: GRM188R60J226MEA0J; Manufacturer: MURATA; Part_Preference: Recommended; Component_Country_Of_Origin: Japan; ID: 2766; ShowFields: YES
C27 C28 C183 = MCD-00100: Capacitor, MLCC, 22uF, 6V3, X5R, +/-20%, 0603, T=0,8mm; Part_Preference: Recommended; Manufacturer: MURATA; Manufacturer_Part_Number: GRM188R60J226MEA0J; Component_Country_Of_Origin: Japan; ID: 2766; ShowFields: YES
C39 C43 C153 C154 C188 = MCD-00095: Capacitor, MLCC, 1uF, 25V, X5R, +/-10%, 0402, T=0.5mm; Part_Preference: Recommended; Manufacturer: MURATA; Manufacturer_Part_Number: GRM155R61E105KA12; Order_Code_RS: 846-7287; Component_Country_Of_Origin: Japan; ShowFields: YES; ID: 2772
C40 = MCD-03140: Capacitor, MLCC, 10uF, 6.3V, X5R, +/-20%, 0402, T=0.5mm; Part_Preference: Recommended; Manufacturer: MURATA; Manufacturer_Part_Number: GRM155R60J106ME05D; ShowFields: YES; ID: 5256; Component_Country_Of_Origin: China, Japan
C91 C141 C142 C156 C189 C190 C208 C209 C217 = MCD-01356: Capacitor, MLCC, 4.7uF, 6V3, X5R, +/-20%, 0402, T=0.5mm; Manufacturer_Part_Number: GRM155R60J475ME47; Manufacturer: MURATA; Part_Preference: Recommended; Order_Code_RS: 814-5230; Component_Country_Of_Origin: Japan; ShowFields: YES; ID: 3456
C155 = MCD-02198: Capacitor, MLCC, 10nF, 50V, X7R, +/-10%, 0402, T=0.5mm; Manufacturer_Part_Number: CC0402KRX7R9BB103; Manufacturer: YAGEO; Part_Preference: Recommended; Order_Code_RS: 6169644; Component_Country_Of_Origin: China; ShowFields: YES; ID: 4298
L1 L6 = MCD-03143: Inductor, 2.2uH, +/-20%, Itemp= 1700mA, Isat= 2400mA, 0R140, 0806, T=1mm; Part_Preference: Recommended; Manufacturer: MURATA; Manufacturer_Part_Number: DFE201610E-2R2M=P2; ShowFields: YES; ID: 5259; Component_Country_Of_Origin: Vietnam
L2 L4 = MCD-03142: Inductor, 0.68uH, +/-20%, Itemp= 3900mA, Isat= 5400mA, 0R031, 1008, T=1.2mm; Part_Preference: Recommended; Manufacturer: MURATA; Manufacturer_Part_Number: DFE252012F-R68M=P2; ShowFields: YES; ID: 5258; Component_Country_Of_Origin: Vietnam
L3 L5 L7 = MCD-03141: Inductor, 0.68uH, +/-20%, Itemp= 3100mA, Isat= 4300mA, 0R043, 0806, T=1mm; Part_Preference: Recommended; Manufacturer: MURATA; Manufacturer_Part_Number: DFE201610E-R68M=P2; ShowFields: YES; ID: 5257; Component_Country_Of_Origin: Vietnam
LD11 = MCD-00588: LED Green, 0603 SMD, Forward Voltage Typ=2V, Max=2.5V; Part_Type: Display; Manufacturer_Part_Number: LG Q396-PS-35; Manufacturer: OSRAM OPTO SEMICONDUCTORS; Alternate_Manufacturer_Part_Number: VLMTG1300-GS08; Alternate_Manufacturer: VISHAY SEMICONDUCTOR OPTO DIVISION; Alternate_Internal_Part_Number: MCD-02400; Part_Preference: Recommended; Provided_By: SUBCO; Component_Country_Of_Origin: Unknown; ID: 3155; ShowFields: YES
LNK1 LNK2 LNK4 LNK7 LNK8 LNK11 = MCD-02777: Track link on PCB 200um width for layout routing; Part_Preference: Recommended; Part_Type: Misc; ID: 4889; ShowFields: YES
R2 R46 R57 R59 R60 R81 = MCD-00052: Resistor,0R,0402,5%,1/16W; Manufacturer_Part_Number: RC0402JR-070RL; Manufacturer: YAGEO; Part_Preference: Recommended; ECCN_US: EAR99; ECCN_EU: NEC; Provided_By: SUBCO; Initial_Board_Reference: mb1274; Order_Code_RS: 618-5804; Component_Country_Of_Origin: China; ID: 2540; ShowFields: YES
R210 = MCD-00441: Resistor,270R,0402,1%,1/16W; Manufacturer_Part_Number: RC0402FR-07270RL; Manufacturer: YAGEO; Part_Preference: Recommended; Provided_By: SUBCO; ECCN_US: EAR99; ECCN_EU: NEC; Component_Country_Of_Origin: China; ID: 2838; ShowFields: YES
U26 = MCD-03000: STPMIC2; Part_Type: IC; Part_Preference: Recommended; Manufacturer: STMICROELECTRONICS; Component_Country_Of_Origin: Unknown; ShowFields: YES; ID: 5116

## Sheet STM32MP25XXAL Power.SchDoc: STM32MP25XXAL Power
size A3; Date: Not used; ApprovedBy: Not used; CheckedBy: Not used; Author: Not used; CompanyName: STMicroelectronics; DrawnBy: Not used; Engineer: Not used; Organization: Not used; Address1: Not used; Address2: Not used; Address3: Not used; Address4: Not used; DocumentNumber: 5; Revision: Not used; SheetNumber: 5; SheetTotal: 7
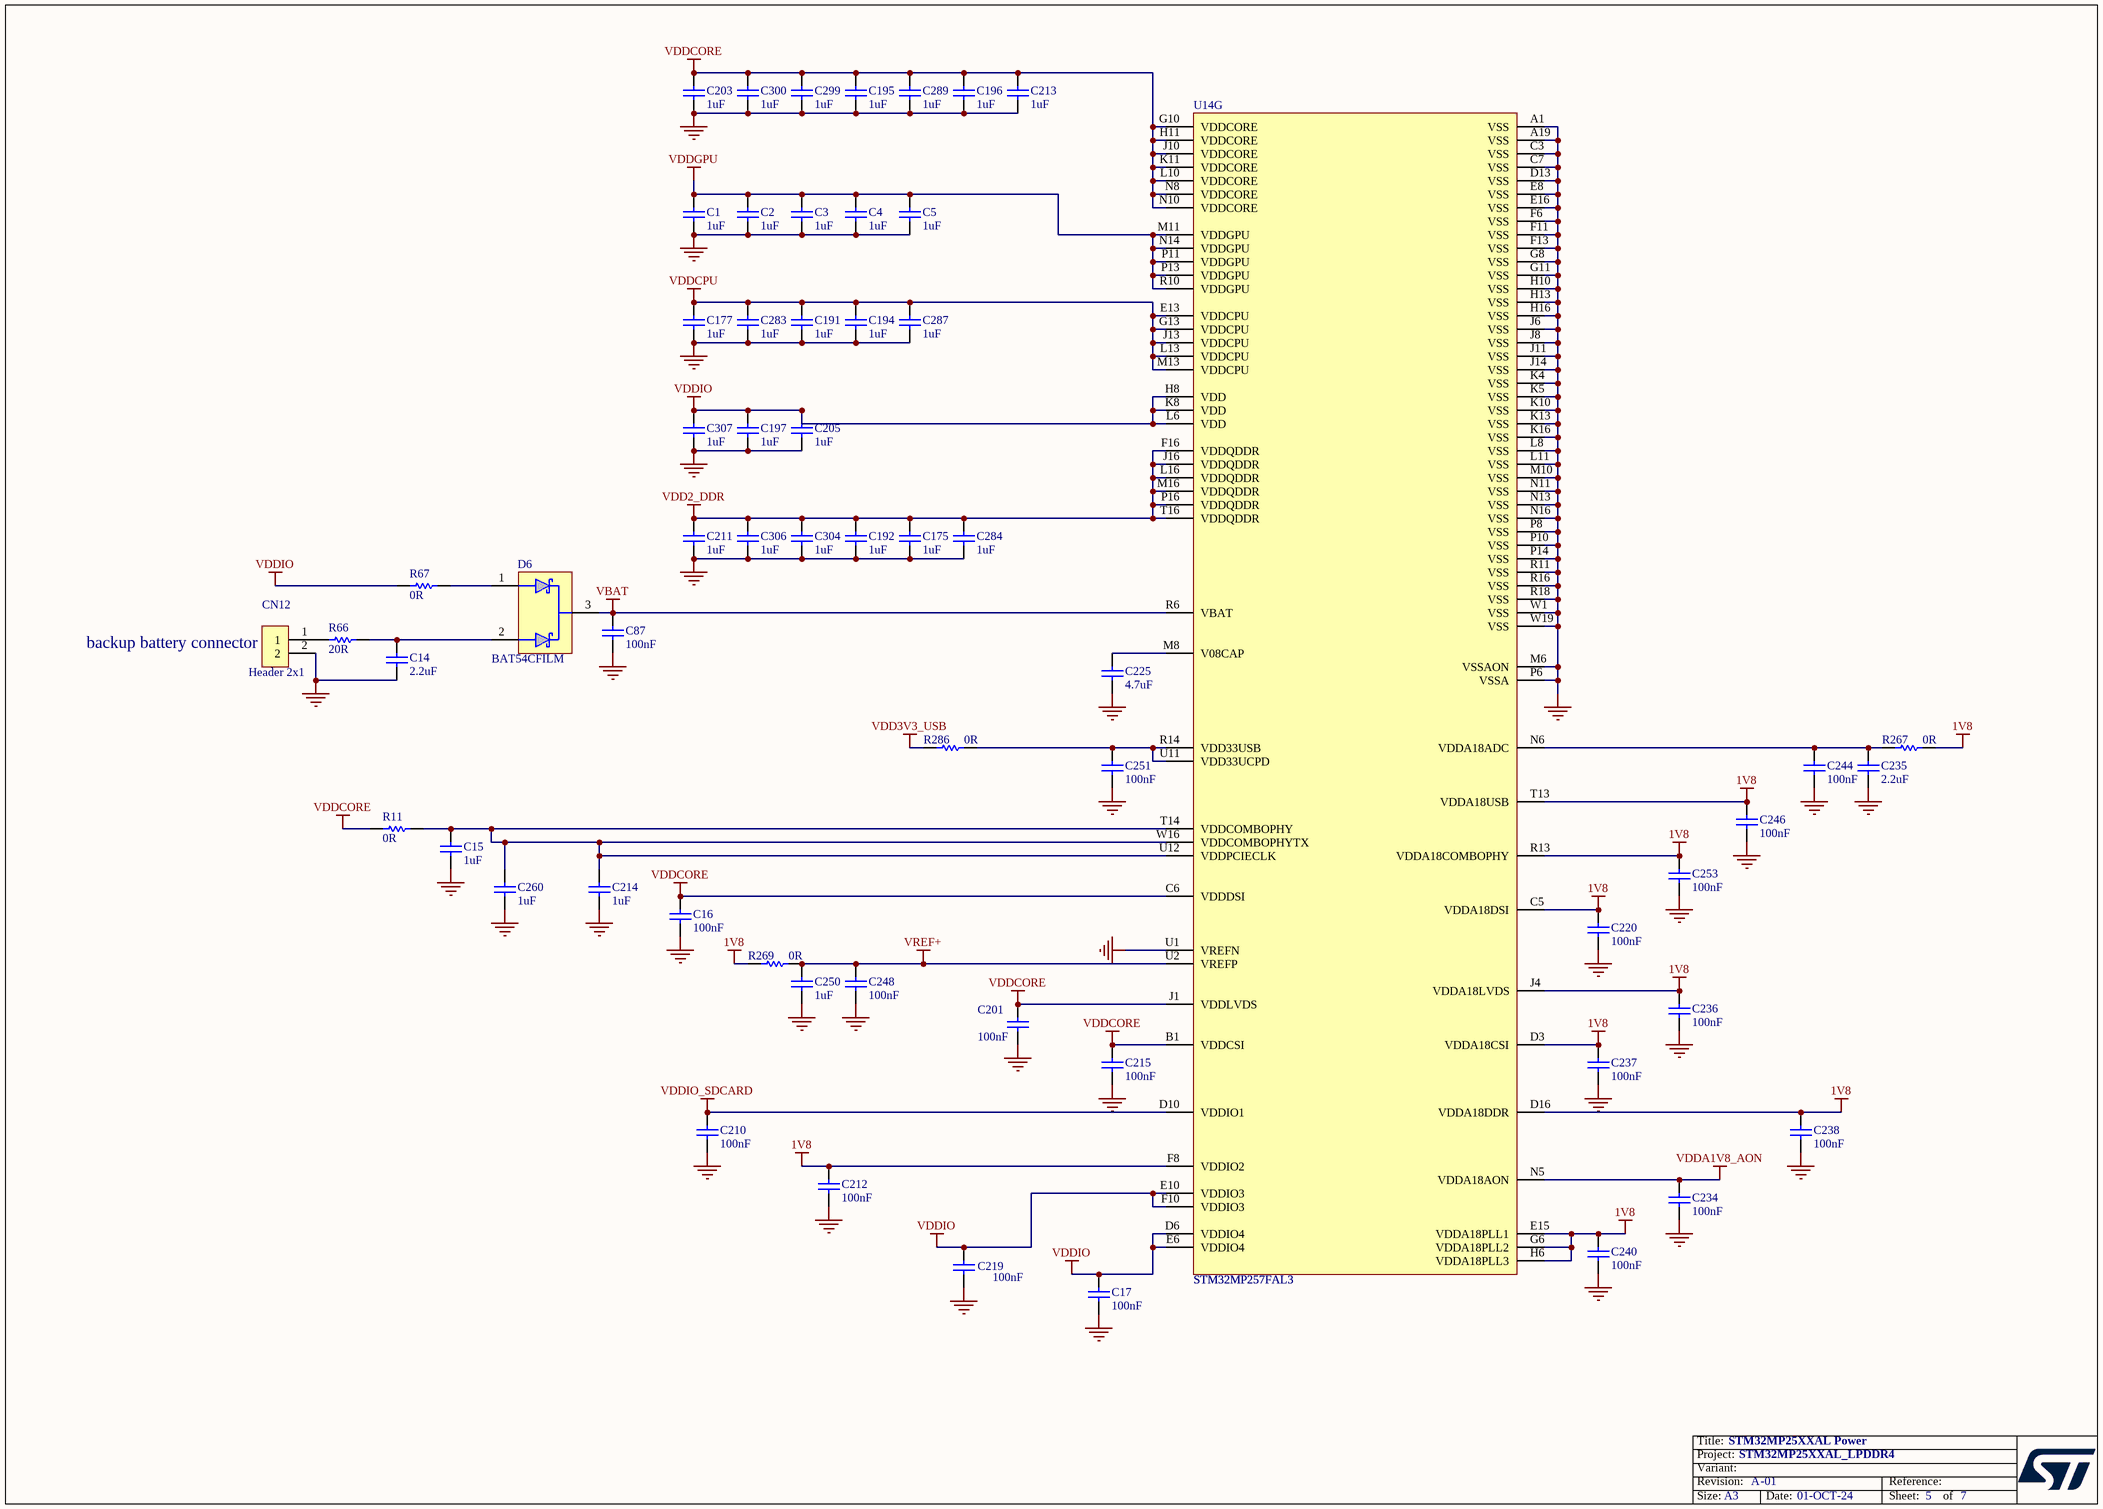
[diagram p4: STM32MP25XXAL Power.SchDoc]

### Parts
C1  1uF  [C0201_MURATA_GRM033_H0P3]
C2  1uF  [C0201_MURATA_GRM033_H0P3]
C3  1uF  [C0201_MURATA_GRM033_H0P3]
C4  1uF  [C0201_MURATA_GRM033_H0P3]
C5  1uF  [C0201_MURATA_GRM033_H0P3]
C14  value 2.2uF  [C0402]  (hidden comment: Capacitor)
C15  value 1uF  [C0201_MURATA_GRM033_H0P3]  (hidden comment: Capacitor)
C16  value 100nF  [C0201_MURATA_GRM033_H0P3]  (hidden comment: Capacitor)
C17  value 100nF  [C0201_MURATA_GRM033_H0P3]  (hidden comment: Capacitor)
C87  value 100nF  [C0402]  (hidden comment: Capacitor)
C175  value 1uF  [C0201_MURATA_GRM033_H0P3]  (hidden comment: Capacitor)
C177  value 1uF  [C0201_MURATA_GRM033_H0P3]  (hidden comment: Capacitor)
C191  value 1uF  [C0201_MURATA_GRM033_H0P3]  (hidden comment: Capacitor)
C192  value 1uF  [C0201_MURATA_GRM033_H0P3]  (hidden comment: Capacitor)
C194  value 1uF  [C0201_MURATA_GRM033_H0P3]  (hidden comment: Capacitor)
C195  value 1uF  [C0201_MURATA_GRM033_H0P3]  (hidden comment: Capacitor)
C196  value 1uF  [C0201_MURATA_GRM033_H0P3]  (hidden comment: Capacitor)
C197  value 1uF  [C0201_MURATA_GRM033_H0P3]  (hidden comment: Capacitor)
C201  value 100nF  [C0201_MURATA_GRM033_H0P3]  (hidden comment: Capacitor)
C203  value 1uF  [C0201_MURATA_GRM033_H0P3]  (hidden comment: Capacitor)
C205  value 1uF  [C0201_MURATA_GRM033_H0P3]  (hidden comment: Capacitor)
C210  value 100nF  [C0201_MURATA_GRM033_H0P3]  (hidden comment: Capacitor)
C211  value 1uF  [C0201_MURATA_GRM033_H0P3]  (hidden comment: Capacitor)
C212  value 100nF  [C0201_MURATA_GRM033_H0P3]  (hidden comment: Capacitor)
C213  value 1uF  [C0201_MURATA_GRM033_H0P3]  (hidden comment: Capacitor)
C214  value 1uF  [C0201_MURATA_GRM033_H0P3]  (hidden comment: Capacitor)
C215  value 100nF  [C0201_MURATA_GRM033_H0P3]  (hidden comment: Capacitor)
C219  value 100nF  [C0201_MURATA_GRM033_H0P3]  (hidden comment: Capacitor)
C220  value 100nF  [C0201_MURATA_GRM033_H0P3]  (hidden comment: Capacitor)
C225  value 4.7uF  [C0201_H0P5]  (hidden comment: Capacitor)
C234  value 100nF  [C0201_MURATA_GRM033_H0P3]  (hidden comment: Capacitor)
C235  value 2.2uF  [C0201_H0P5]  (hidden comment: Capacitor)
C236  value 100nF  [C0201_MURATA_GRM033_H0P3]  (hidden comment: Capacitor)
C237  value 100nF  [C0201_MURATA_GRM033_H0P3]  (hidden comment: Capacitor)
C238  value 100nF  [C0201_MURATA_GRM033_H0P3]  (hidden comment: Capacitor)
C240  value 100nF  [C0201_MURATA_GRM033_H0P3]  (hidden comment: Capacitor)
C244  value 100nF  [C0201_MURATA_GRM033_H0P3]  (hidden comment: Capacitor)
C246  value 100nF  [C0201_MURATA_GRM033_H0P3]  (hidden comment: Capacitor)
C248  value 100nF  [C0201_MURATA_GRM033_H0P3]  (hidden comment: Capacitor)
C250  value 1uF  [C0201_MURATA_GRM033_H0P3]  (hidden comment: Capacitor)
C251  value 100nF  [C0201_MURATA_GRM033_H0P3]  (hidden comment: Capacitor)
C253  value 100nF  [C0201_MURATA_GRM033_H0P3]  (hidden comment: Capacitor)
C260  value 1uF  [C0201_MURATA_GRM033_H0P3]  (hidden comment: Capacitor)
C283  value 1uF  [C0201_MURATA_GRM033_H0P3]  (hidden comment: Capacitor)
C284  value 1uF  [C0201_MURATA_GRM033_H0P3]  (hidden comment: Capacitor)
C287  value 1uF  [C0201_MURATA_GRM033_H0P3]  (hidden comment: Capacitor)
C289  value 1uF  [C0201_MURATA_GRM033_H0P3]  (hidden comment: Capacitor)
C299  value 1uF  [C0201_MURATA_GRM033_H0P3]  (hidden comment: Capacitor)
C300  value 1uF  [C0201_MURATA_GRM033_H0P3]  (hidden comment: Capacitor)
C304  value 1uF  [C0201_MURATA_GRM033_H0P3]  (hidden comment: Capacitor)
C306  value 1uF  [C0201_MURATA_GRM033_H0P3]  (hidden comment: Capacitor)
C307  value 1uF  [C0201_MURATA_GRM033_H0P3]  (hidden comment: Capacitor)
CN12  Header 2x1  [CON_MOLEX_53047-0210]
D6  value BAT54CFILM  [DIO_SOT23]  (hidden comment: DIODE_3P_DUAL_COMMON_CATHODE)
R11  value 0R  [R0603]  (hidden comment: Resistor)
R66  value 20R  [R0402]  (hidden comment: Resistor)
R67  value 0R  [R0402]  (hidden comment: Resistor)
R267  value 0R  [R0402]  (hidden comment: Resistor)
R269  value 0R  [R0402]  (hidden comment: Resistor)
R286  value 0R  [R0402]  (hidden comment: Resistor)
U14  STM32MP257FAL3  [ICC_VFBGA361_10X10_P050]  (part G of 8)

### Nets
1V8: C212.2 C220.2 C236.2 C237.2 C238.2 C240.2 C246.2 C253.2 R267.2 R269.1 U14.C5(VDDA18DSI) U14.D3(VDDA18CSI) U14.D16(VDDA18DDR) U14.E15(VDDA18PLL1) U14.F8(VDDIO2) U14.G6(VDDA18PLL2) U14.H6(VDDA18PLL3) U14.J4(VDDA18LVDS) U14.R13(VDDA18COMBOPHY) U14.T13(VDDA18USB)
GND: C1.1 C2.1 C3.1 C4.1 C5.1 C14.1 C15.1 C16.1 C17.1 C87.1 C175.2 C177.2 C191.2 C192.2 C194.1 C195.2 C196.1 C197.1 C201.1 C203.2 C205.1 C210.1 C211.2 C212.1 C213.1 C214.1 C215.1 C219.1 C220.1 C225.1 C234.1 C235.1 C236.1 C237.1 C238.1 C240.1 C244.1 C246.1 C248.1 C250.1 C251.1 C253.1 C260.1 C283.1 C284.2 C287.1 C289.1 C299.1 C300.1 C304.2 C306.2 C307.2 CN12.2 U14.A1(VSS) U14.A19(VSS) U14.C3(VSS) U14.C7(VSS) U14.D13(VSS) U14.E8(VSS) U14.E16(VSS) U14.F6(VSS) U14.F11(VSS) U14.F13(VSS) U14.G8(VSS) U14.G11(VSS) U14.H10(VSS) U14.H13(VSS) U14.H16(VSS) U14.J6(VSS) U14.J8(VSS) U14.J11(VSS) U14.J14(VSS) U14.K4(VSS) U14.K5(VSS) U14.K10(VSS) U14.K13(VSS) U14.K16(VSS) U14.L8(VSS) U14.L11(VSS) U14.M6(VSSAON) U14.M10(VSS) U14.N11(VSS) U14.N13(VSS) U14.N16(VSS) U14.P6(VSSA) U14.P8(VSS) U14.P10(VSS) U14.P14(VSS) U14.R11(VSS) U14.R16(VSS) U14.R18(VSS) U14.U1(VREFN) U14.W1(VSS) U14.W19(VSS)
VBAT: C87.2 D6.3 U14.R6(VBAT)
VDD2_DDR: C175.1 C192.1 C211.1 C284.1 C304.1 C306.1 U14.F16(VDDQDDR) U14.J16(VDDQDDR) U14.L16(VDDQDDR) U14.M16(VDDQDDR) U14.P16(VDDQDDR) U14.T16(VDDQDDR)
VDD3V3_USB: R286.1
VDDA1V8_AON: C234.2 U14.N5(VDDA18AON)
VDDCORE: C16.2 C195.1 C196.2 C201.2 C203.1 C213.2 C215.2 C289.2 C299.2 C300.2 R11.1 U14.B1(VDDCSI) U14.C6(VDDDSI) U14.G10(VDDCORE) U14.H11(VDDCORE) U14.J1(VDDLVDS) U14.J10(VDDCORE) U14.K11(VDDCORE) U14.L10(VDDCORE) U14.N8(VDDCORE) U14.N10(VDDCORE)
VDDCPU: C177.1 C191.1 C194.2 C283.2 C287.2 U14.E13(VDDCPU) U14.G13(VDDCPU) U14.J13(VDDCPU) U14.L13(VDDCPU) U14.M13(VDDCPU)
VDDGPU: C1.2 C2.2 C3.2 C4.2 C5.2 U14.M11(VDDGPU) U14.N14(VDDGPU) U14.P11(VDDGPU) U14.P13(VDDGPU) U14.R10(VDDGPU)
VDDIO: C17.2 C197.2 C205.2 C219.2 C307.1 R67.2 U14.D6(VDDIO4) U14.E6(VDDIO4) U14.E10(VDDIO3) U14.F10(VDDIO3) U14.H8(VDD) U14.K8(VDD) U14.L6(VDD)
VDDIO_SDCARD: C210.2 U14.D10(VDDIO1)
VREF+: C248.2 C250.2 R269.2 U14.U2(VREFP)
NetC14_2: C14.2 D6.2 R66.2
NetC15_2: C15.2 C214.2 C260.2 R11.2 U14.T14(VDDCOMBOPHY) U14.U12(VDDPCIECLK) U14.W16(VDDCOMBOPHYTX)
NetC225_2: C225.2 U14.M8(V08CAP)
NetC235_2: C235.2 C244.2 R267.1 U14.N6(VDDA18ADC)
NetC251_2: C251.2 R286.2 U14.R14(VDD33USB) U14.U11(VDD33UCPD)
NetCN12_1: CN12.1 R66.1
NetD6_1: D6.1 R67.1

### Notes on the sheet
- (near CN12) backup battery connector

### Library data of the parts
C1-C5 = MCD-02377: Capacitor, MLCC, 1uF, 6.3V, X5R, +/-20%, 0201, T=0,3mm; Part_Preference: Recommended; Manufacturer: MURATA; Manufacturer_Part_Number: GRM033R60J105MEA2; Order_Code_RS: 820-0643; Component_Country_Of_Origin: Japan°; ShowFields: YES; ID: 4483
C14 = MCD-01823: Capacitor, MLCC, 2.2uF, 6V3, X5R,+/-10%, 0402, T=0.5mm; Part_Preference: Recommended; Manufacturer: MURATA; Manufacturer_Part_Number: GRM155R60J225KE95D; Partial_Alternate_Internal_Part_Number: MCD-03566; Order_Code_RS: 172-6478; Component_Country_Of_Origin: Japan°°; ID: 3923; ShowFields: YES
C15 C214 C250 C260 = MCD-02377: Capacitor, MLCC, 1uF, 6.3V, X5R, +/-20%, 0201, T=0,3mm; Manufacturer_Part_Number: GRM033R60J105MEA2; Manufacturer: MURATA; Part_Preference: Recommended; Order_Code_RS: 820-0643; Component_Country_Of_Origin: Japan°; ID: 4483; ShowFields: YES
C16 C17 C201 C210 C212 C215 C219 C220 C234 C236-C238 C240 C244 C246 C248 C251 C253 = MCD-01535: Capacitor, MLCC,100nF, 10V, X5R, +/-10%, 0201, T=0.3mm; Part_Preference: Recommended; Manufacturer: MURATA; Manufacturer_Part_Number: GRM033R61A104KE15; Order_Code_RS: 790-2742; Component_Country_Of_Origin: Japan°°; ID: 3635; ShowFields: YES
C87 = MCD-00006: Capacitor, MLCC, 100nF, 16V, X7R, +/-10%, 0402, T=0.5mm; Manufacturer_Part_Number: CC0402KRX7R7BB104; Manufacturer: YAGEO; Part_Preference: Recommended; Partial_Alternate_Internal_Part_Number: MCD-03299; Order_Code_RS: 9402047; Component_Country_Of_Origin: China; ID: 2474; ShowFields: YES
C175 C177 C191 C192 C194-C197 C203 C205 C211 C213 C283 C284 C287 C289 C299 C300 C304 C306 C307 = MCD-01533: Capacitor, MLCC, 1uF, 6V3, X5R, +/-20%, 0201, T=0.3mm; Part_Preference: Not recommended; Manufacturer: MURATA; Manufacturer_Part_Number: GRM033R60J105ME11; Component_Country_Of_Origin: Japan; ShowFields: YES; ID: 3633
C225 = MCD-01534: Capacitor, MLCC, 4,7uF, 6V3, X5R, +/-20%, 0201, T=0.5mm; Part_Preference: Recommended; Manufacturer: MURATA; Manufacturer_Part_Number: GRM035R60J475ME15; Component_Country_Of_Origin: Japan°°; ID: 3634; ShowFields: YES
C235 = MCD-02235: Capacitor, MLCC, 2.2uF, 10V, X5R,+/-10%, 0201, T=0.5mm; Part_Preference: Recommended; Manufacturer: MURATA; Manufacturer_Part_Number: GRM033R61A225KE47D; Order_Code_RS: NA; Component_Country_Of_Origin: Japan°°; ShowFields: YES; ID: 4335
CN12 = MCD-00655: Header, 2x1, 1.25mm, VR, TH, T=2.25mm/2.3mm; Part_Type: Connector; Manufacturer_Part_Number: 53047-0210; Manufacturer: MOLEX; BMS_Part_Number: 9083002; Part_Preference: Recommended; Order_Code_RS: 279-9213; Component_Country_Of_Origin: Unknown; ID: 3091; ShowFields: YES
D6 = MCD-03280: Diode, Schottky, Dual Common Cathode, 0V3, 300mA, 40V, SOT-23; Part_Preference: Recommended; Manufacturer: STMICROELECTRONICS; Order_Code_RS: 795-8397; Component_Country_Of_Origin: China; ShowFields: YES; ID: 5396
R11 = MCD-00056: Resistor, 0R, 0603, +/-5%, 1/10W; Part_Preference: Recommended; Manufacturer: YAGEO; Manufacturer_Part_Number: RC0603JR-070RL; Order_Code_RS: 9233130RL; Component_Country_Of_Origin: China; ShowFields: YES; ID: 2536
R66 = MCD-00058: Resistor, 20R, 0402, +/-1%, 1/16W; BMS_Part_Number: 9131027; Part_Preference: Recommended; Manufacturer: YAGEO; Manufacturer_Part_Number: RC0402FR-0720RL; Order_Code_RS: 1799192; Component_Country_Of_Origin: China; ID: 2537; ShowFields: YES
R67 = MCD-00052: Resistor, 0R, 0402, +/-5%, 1/16W; Manufacturer_Part_Number: RC0402JR-070RL; Manufacturer: YAGEO; Part_Preference: Recommended; Order_Code_RS: 9232516RL; Component_Country_Of_Origin: China; ShowFields: YES; ID: 2540
R267 R269 R286 = MCD-00052: as R3 on sheet STM32MP25XXAL I_Os
U14 = MCD-03768: as U14 on sheet STM32MP25XXAL I_Os

## Sheet eMMC.SchDoc: eMMC
size A3; Date: Not used; ApprovedBy: Not used; CheckedBy: Not used; Author: Not used; CompanyName: STMicroelectronics; DrawnBy: Not used; Engineer: Not used; Organization: Not used; Address1: Not used; Address2: Not used; Address3: Not used; Address4: Not used; DocumentNumber: 7; Revision: Not used; SheetNumber: 7; SheetTotal: 7
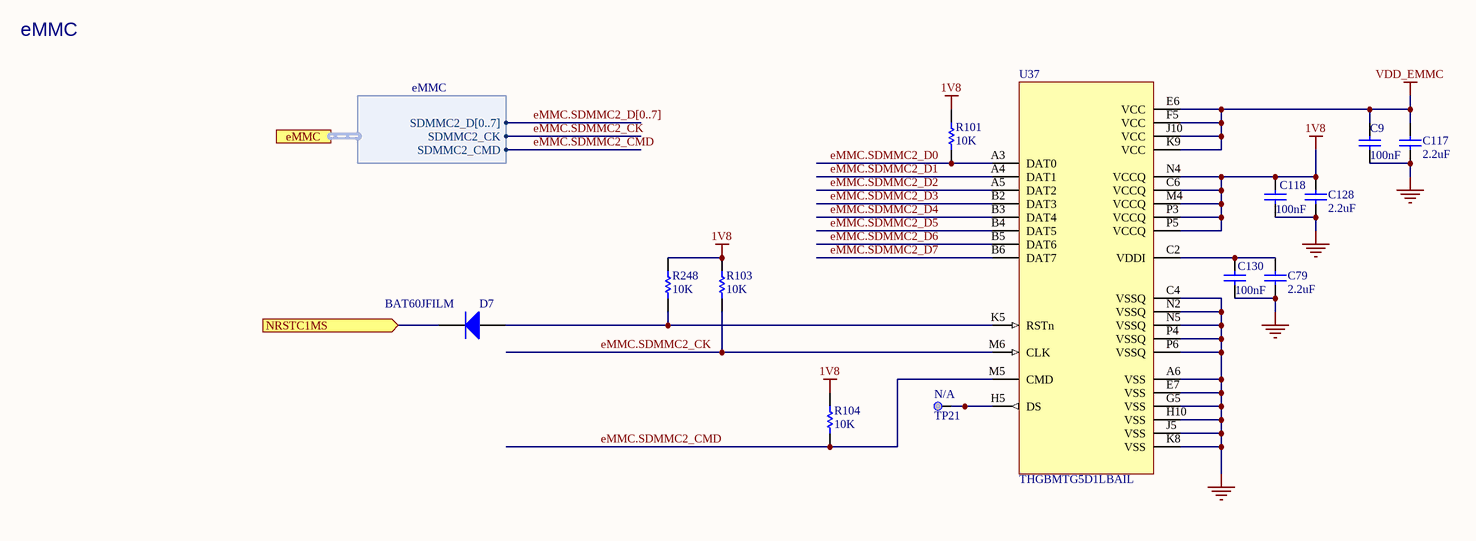
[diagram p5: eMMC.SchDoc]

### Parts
C9  value 100nF  [C0402]  (hidden comment: Capacitor)
C79  value 2.2uF  [C0402]  (hidden comment: Capacitor)
C117  value 2.2uF  [C0402]  (hidden comment: Capacitor)
C118  value 100nF  [C0402]  (hidden comment: Capacitor)
C128  value 2.2uF  [C0402]  (hidden comment: Capacitor)
C130  value 100nF  [C0402]  (hidden comment: Capacitor)
D7  BAT60JFILM  [DIO_SOD323]
R101  value 10K  [R0402]  (hidden comment: Resistor)
R103  value 10K  [R0402]  (hidden comment: Resistor)
R104  value 10K  [R0402]  (hidden comment: Resistor)
R248  value 10K  [R0402]  (hidden comment: Resistor)
TP21  Test Point  [TP_SMD_1MM]  (value not drawn)  (no BOM)
U37  value THGBMTG5D1LBAIL  [ICC_P-WFBGA153_13X11P5_P050]  (hidden comment: eMMC_THGBMTG5D1LBAIL)

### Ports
eMMC (harness eMMC), NRSTC1MS (in)

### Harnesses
eMMC: SDMMC2_CK, SDMMC2_CMD, SDMMC2_D[0..7]

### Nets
1V8: C118.2 C128.2 R101.2 R103.2 R104.2 R248.2 U37.C6(VCCQ) U37.M4(VCCQ) U37.N4(VCCQ) U37.P3(VCCQ) U37.P5(VCCQ)
GND: C9.1 C79.1 C117.1 C118.1 C128.1 C130.1 U37.A6(VSS) U37.C4(VSSQ) U37.E7(VSS) U37.G5(VSS) U37.H10(VSS) U37.J5(VSS) U37.K8(VSS) U37.N2(VSSQ) U37.N5(VSSQ) U37.P4(VSSQ) U37.P6(VSSQ)
VDD_EMMC: C9.2 C117.2 U37.E6(VCC) U37.F5(VCC) U37.J10(VCC) U37.K9(VCC)
eMMC.SDMMC2_CK: R103.1 U37.M6(CLK) ; port eMMC.SDMMC2_CK
eMMC.SDMMC2_CMD: R104.1 U37.M5(CMD) ; port eMMC.SDMMC2_CMD
eMMC.SDMMC2_D0: R101.1 U37.A3(DAT0)
eMMC.SDMMC2_D1: U37.A4(DAT1)
eMMC.SDMMC2_D2: U37.A5(DAT2)
eMMC.SDMMC2_D3: U37.B2(DAT3)
eMMC.SDMMC2_D4: U37.B3(DAT4)
eMMC.SDMMC2_D5: U37.B4(DAT5)
eMMC.SDMMC2_D6: U37.B5(DAT6)
eMMC.SDMMC2_D7: U37.B6(DAT7)
NRSTC1MS: D7.2(K) ; port NRSTC1MS
NetC79_2: C79.2 C130.2 U37.C2(VDDI)
NetD7_1: D7.1(A) R248.1 U37.K5(RSTn)
NetTP21_1: TP21.1 U37.H5(DS)

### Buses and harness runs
bus eMMC.SDMMC2_D[0..7]

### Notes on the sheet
- eMMC

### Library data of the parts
C9 C118 C130 = MCD-00006: Capacitor, MLCC, 100nF, 16V, X7R, +/-10%, 0402, T=0.5mm; Part_Preference: Recommended; Manufacturer: YAGEO; Manufacturer_Part_Number: CC0402KRX7R7BB104; Partial_Alternate_Internal_Part_Number: MCD-03299; Order_Code_RS: 9402047; Component_Country_Of_Origin: China; ID: 2474; ShowFields: YES
C79 C117 C128 = MCD-02606: Capacitor, MLCC, 2.2uF, 6.3V, X5R, +/-10%, 0402, T=0.5mm; Part_Preference: Recommended; Manufacturer: YAGEO; Manufacturer_Part_Number: CC0402KRX5R5BB225; Order_Code_RS: 1992205; ShowFields: YES; ID: 4712; Component_Country_Of_Origin: China°
D7 = MCD-00034: Diode, Schottky, 0V53, 1A, 10V, SOD323; BMS_Part_Number: 9151097; Part_Preference: Recommended; Manufacturer: STMICROELECTRONICS; Manufacturer_HQ_COO: EU; Component_Country_Of_Origin: China; ShowFields: YES; ID: 2483; Order_Code_RS: 714-6879
R101 R103 R104 R248 = MCD-00053: Resistor, 10K, 0402, +/-1%, 1/16W; Manufacturer_Part_Number: RC0402FR-0710KL; Manufacturer: YAGEO; BMS_Part_Number: 9131590; Part_Preference: Recommended; Order_Code_RS: 9239359; Component_Country_Of_Origin: China; ID: 2539; ShowFields: YES
TP21 = MCD-00074: Test Point, SMD, 1mm; Part_Type: Misc; Part_Preference: Recommended; Component_Country_Of_Origin: Unknown; ID: 2518; ShowFields: YES
U37 = MCD-02799: Memory, eMMC, 3V3, 4Gbit, 52MHz; Part_Type: IC; Part_Preference: Not recommended; Manufacturer: KIOXIA; ShowFields: YES; ID: 4911; Component_Country_Of_Origin: Unknown

## Sheet LPDDR4_16bits.SchDoc: LPDDR4_16bits
size A3; Date: Not used; ApprovedBy: Not used; CheckedBy: Not used; Author: Not used; CompanyName: STMicroelectronics; DrawnBy: Not used; Engineer: Not used; Organization: Not used; Address1: Not used; Address2: Not used; Address3: Not used; Address4: Not used; DocumentNumber: 6; Revision: Not used; SheetNumber: 6; SheetTotal: 7
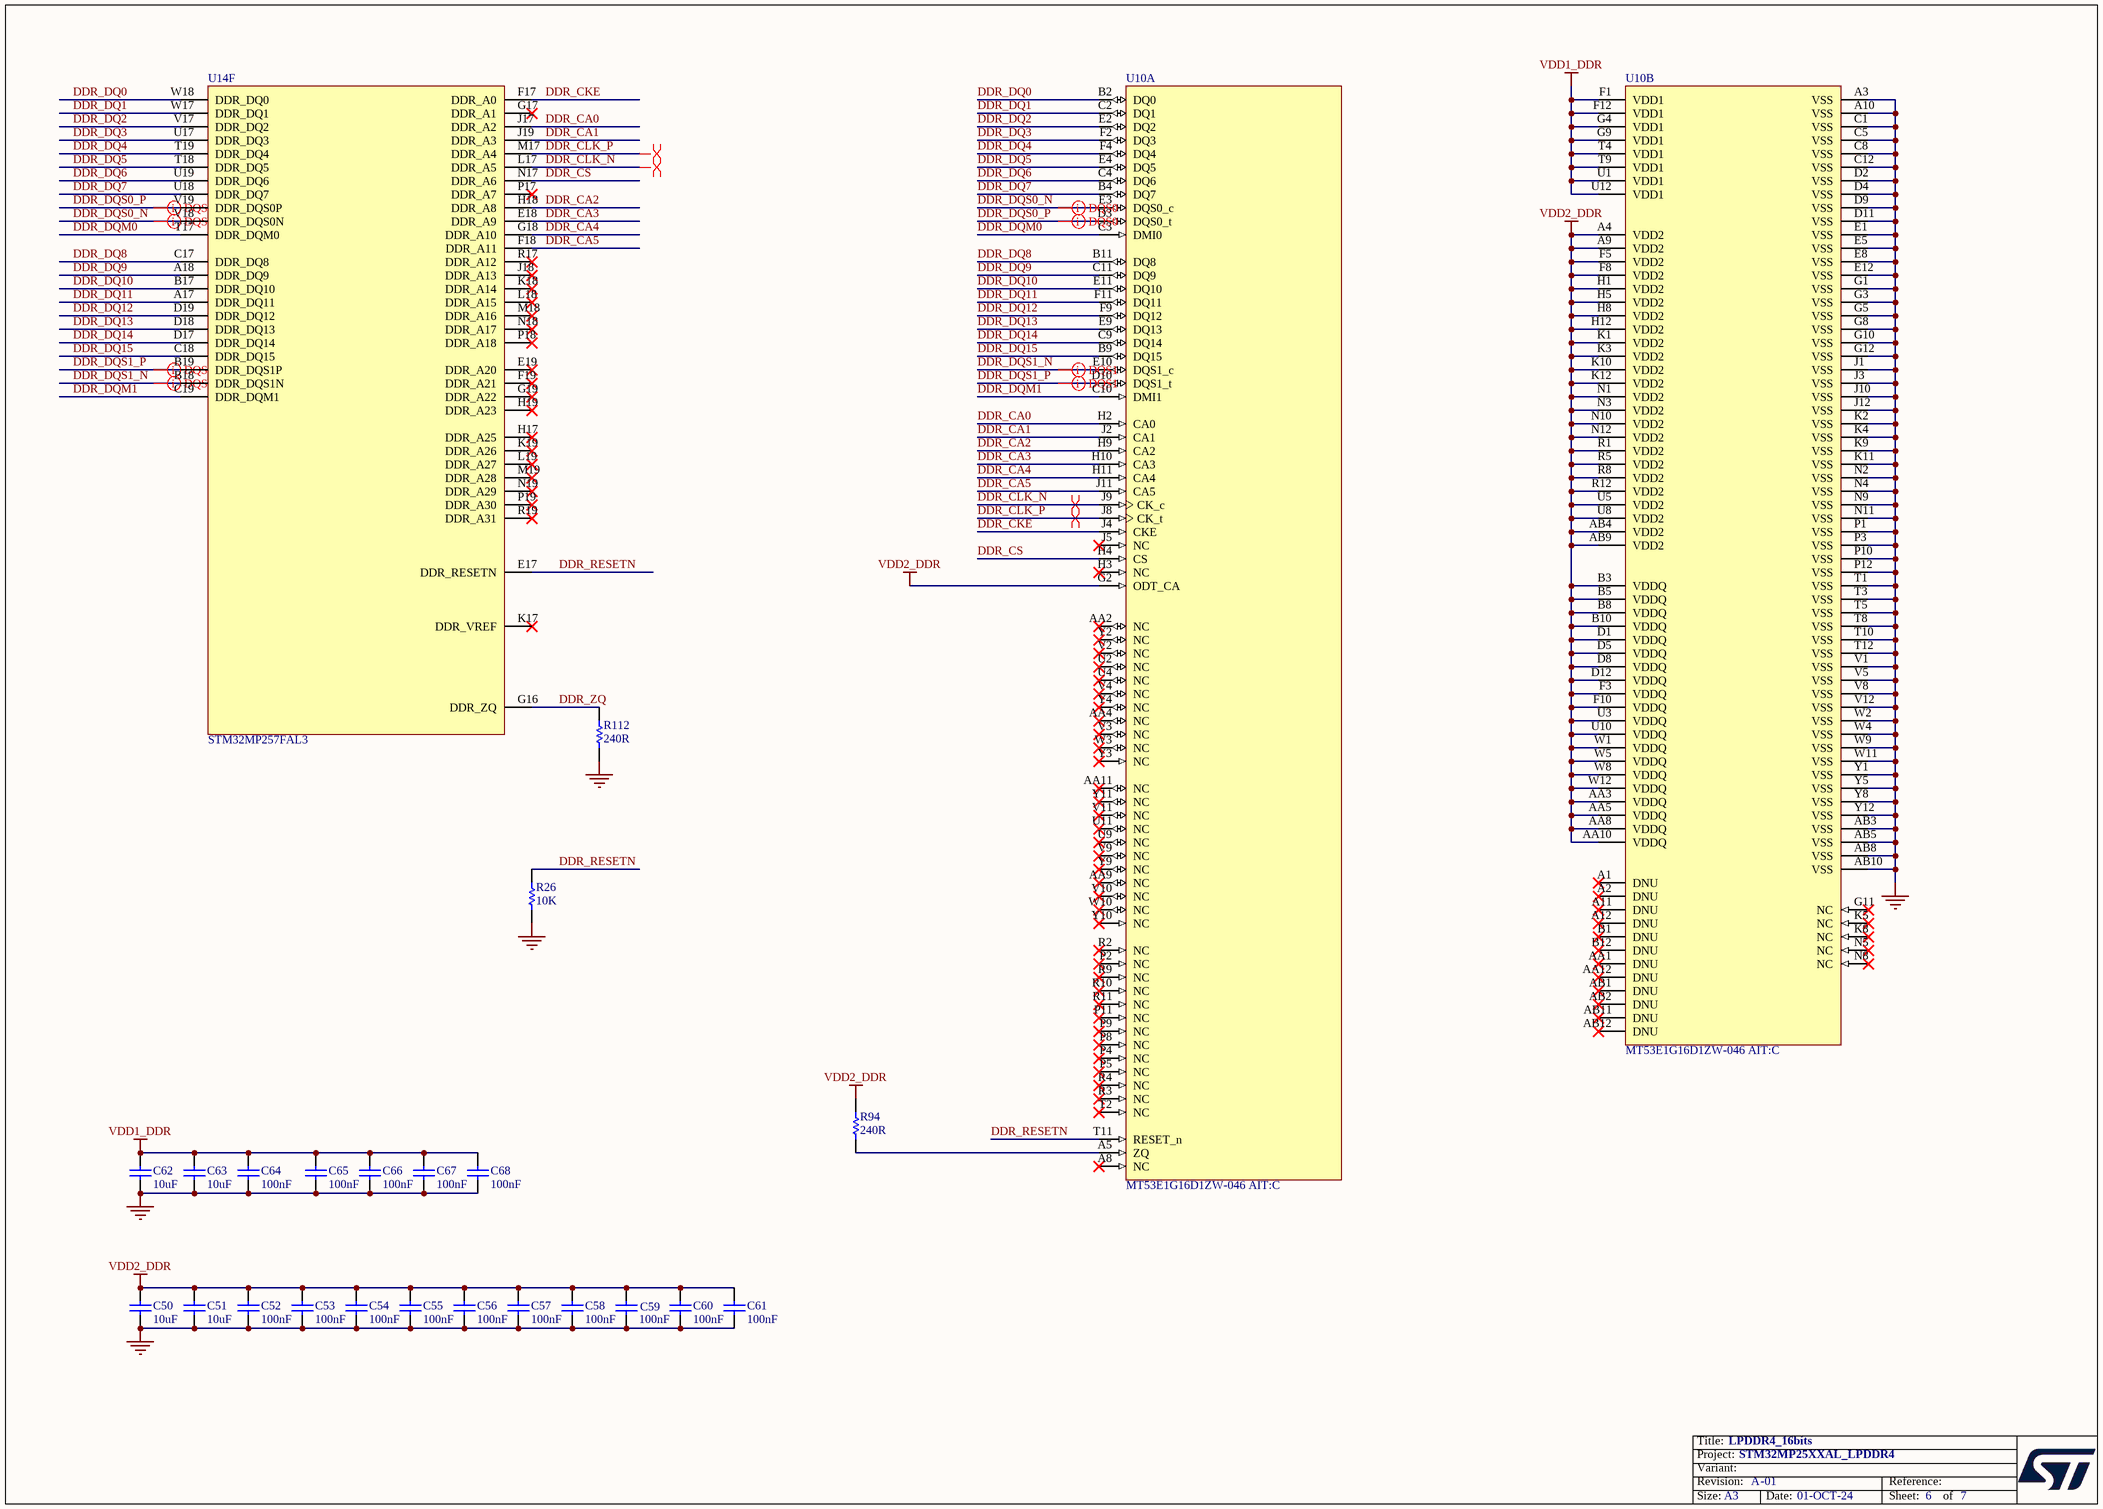
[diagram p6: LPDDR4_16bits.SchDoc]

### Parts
C50  value 10uF  [C0603]  (hidden comment: Capacitor)
C51  value 10uF  [C0603]  (hidden comment: Capacitor)
C52  value 100nF  [C0402]  (hidden comment: Capacitor)
C53  value 100nF  [C0402]  (hidden comment: Capacitor)
C54  value 100nF  [C0402]  (hidden comment: Capacitor)
C55  value 100nF  [C0402]  (hidden comment: Capacitor)
C56  value 100nF  [C0402]  (hidden comment: Capacitor)
C57  value 100nF  [C0402]  (hidden comment: Capacitor)
C58  value 100nF  [C0402]  (hidden comment: Capacitor)
C59  value 100nF  [C0402]  (hidden comment: Capacitor)
C60  value 100nF  [C0402]  (hidden comment: Capacitor)
C61  value 100nF  [C0402]  (hidden comment: Capacitor)
C62  value 10uF  [C0603]  (hidden comment: Capacitor)
C63  value 10uF  [C0603]  (hidden comment: Capacitor)
C64  value 100nF  [C0402]  (hidden comment: Capacitor)
C65  value 100nF  [C0402]  (hidden comment: Capacitor)
C66  value 100nF  [C0402]  (hidden comment: Capacitor)
C67  value 100nF  [C0402]  (hidden comment: Capacitor)
C68  value 100nF  [C0402]  (hidden comment: Capacitor)
R26  value 10K  [R0402]  (hidden comment: Resistor)
R94  value 240R  [R0201_H0P23]  (hidden comment: Resistor)
R112  value 240R  [R0201_H0P23]  (hidden comment: Resistor)
U10  MT53E1G16D1ZW-046 AIT:C  [ICC_TFBGA200_10X14P5_P080_H1P05]  (parts A,B of 2)
U14  STM32MP257FAL3  [ICC_VFBGA361_10X10_P050]  (part F of 8)

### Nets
GND: C50.1 C51.1 C52.1 C53.2 C54.2 C55.2 C56.2 C57.2 C58.2 C59.2 C60.2 C61.2 C62.1 C63.1 C64.1 C65.1 C66.1 C67.1 C68.1 R26.1 R112.1 U10.A3(VSS) U10.A10(VSS) U10.AB3(VSS) U10.AB5(VSS) U10.AB8(VSS) U10.AB10(VSS) U10.C1(VSS) U10.C5(VSS) U10.C8(VSS) U10.C12(VSS) U10.D2(VSS) U10.D4(VSS) U10.D9(VSS) U10.D11(VSS) U10.E1(VSS) U10.E5(VSS) U10.E8(VSS) U10.E12(VSS) U10.G1(VSS) U10.G3(VSS) U10.G5(VSS) U10.G8(VSS) U10.G10(VSS) U10.G12(VSS) U10.J1(VSS) U10.J3(VSS) U10.J10(VSS) U10.J12(VSS) U10.K2(VSS) U10.K4(VSS) U10.K9(VSS) U10.K11(VSS) U10.N2(VSS) U10.N4(VSS) U10.N9(VSS) U10.N11(VSS) U10.P1(VSS) U10.P3(VSS) U10.P10(VSS) U10.P12(VSS) U10.T1(VSS) U10.T3(VSS) U10.T5(VSS) U10.T8(VSS) U10.T10(VSS) U10.T12(VSS) U10.V1(VSS) U10.V5(VSS) U10.V8(VSS) U10.V12(VSS) U10.W2(VSS) U10.W4(VSS) U10.W9(VSS) U10.W11(VSS) U10.Y1(VSS) U10.Y5(VSS) U10.Y8(VSS) U10.Y12(VSS)
VDD1_DDR: C62.2 C63.2 C64.2 C65.2 C66.2 C67.2 C68.2 U10.F1(VDD1) U10.F12(VDD1) U10.G4(VDD1) U10.G9(VDD1) U10.T4(VDD1) U10.T9(VDD1) U10.U1(VDD1) U10.U12(VDD1)
VDD2_DDR: C50.2 C51.2 C52.2 C53.1 C54.1 C55.1 C56.1 C57.1 C58.1 C59.1 C60.1 C61.1 R94.2 U10.A4(VDD2) U10.A9(VDD2) U10.AA3(VDDQ) U10.AA5(VDDQ) U10.AA8(VDDQ) U10.AA10(VDDQ) U10.AB4(VDD2) U10.AB9(VDD2) U10.B3(VDDQ) U10.B5(VDDQ) U10.B8(VDDQ) U10.B10(VDDQ) U10.D1(VDDQ) U10.D5(VDDQ) U10.D8(VDDQ) U10.D12(VDDQ) U10.F3(VDDQ) U10.F5(VDD2) U10.F8(VDD2) U10.F10(VDDQ) U10.G2(ODT_CA) U10.H1(VDD2) U10.H5(VDD2) U10.H8(VDD2) U10.H12(VDD2) U10.K1(VDD2) U10.K3(VDD2) U10.K10(VDD2) U10.K12(VDD2) U10.N1(VDD2) U10.N3(VDD2) U10.N10(VDD2) U10.N12(VDD2) U10.R1(VDD2) U10.R5(VDD2) U10.R8(VDD2) U10.R12(VDD2) U10.U3(VDDQ) U10.U5(VDD2) U10.U8(VDD2) U10.U10(VDDQ) U10.W1(VDDQ) U10.W5(VDDQ) U10.W8(VDDQ) U10.W12(VDDQ)
DDR_CA0: U10.H2(CA0) U14.J17(DDR_A2)
DDR_CA1: U10.J2(CA1) U14.J19(DDR_A3)
DDR_CA2: U10.H9(CA2) U14.H18(DDR_A8)
DDR_CA3: U10.H10(CA3) U14.E18(DDR_A9)
DDR_CA4: U10.H11(CA4) U14.G18(DDR_A10)
DDR_CA5: U10.J11(CA5) U14.F18(DDR_A11)
DDR_CKE: U10.J4(CKE) U14.F17(DDR_A0)
DDR_CLK_N: U10.J9(CK_c) U14.L17(DDR_A5)
DDR_CLK_P: U10.J8(CK_t) U14.M17(DDR_A4)
DDR_CS: U10.H4(CS) U14.N17(DDR_A6)
DDR_DQ0: U10.B2(DQ0) U14.W18(DDR_DQ0)
DDR_DQ1: U10.C2(DQ1) U14.W17(DDR_DQ1)
DDR_DQ2: U10.E2(DQ2) U14.V17(DDR_DQ2)
DDR_DQ3: U10.F2(DQ3) U14.U17(DDR_DQ3)
DDR_DQ4: U10.F4(DQ4) U14.T19(DDR_DQ4)
DDR_DQ5: U10.E4(DQ5) U14.T18(DDR_DQ5)
DDR_DQ6: U10.C4(DQ6) U14.U19(DDR_DQ6)
DDR_DQ7: U10.B4(DQ7) U14.U18(DDR_DQ7)
DDR_DQ8: U10.B11(DQ8) U14.C17(DDR_DQ8)
DDR_DQ9: U10.C11(DQ9) U14.A18(DDR_DQ9)
DDR_DQ10: U10.E11(DQ10) U14.B17(DDR_DQ10)
DDR_DQ11: U10.F11(DQ11) U14.A17(DDR_DQ11)
DDR_DQ12: U10.F9(DQ12) U14.D19(DDR_DQ12)
DDR_DQ13: U10.E9(DQ13) U14.D18(DDR_DQ13)
DDR_DQ14: U10.C9(DQ14) U14.D17(DDR_DQ14)
DDR_DQ15: U10.B9(DQ15) U14.C18(DDR_DQ15)
DDR_DQM0: U10.C3(DMI0) U14.T17(DDR_DQM0)
DDR_DQM1: U10.C10(DMI1) U14.C19(DDR_DQM1)
DDR_DQS0_N: U10.E3(DQS0_c) U14.V18(DDR_DQS0N)
DDR_DQS0_P: U10.D3(DQS0_t) U14.V19(DDR_DQS0P)
DDR_DQS1_N: U10.E10(DQS1_c) U14.B18(DDR_DQS1N)
DDR_DQS1_P: U10.D10(DQS1_t) U14.B19(DDR_DQS1P)
DDR_RESETN: R26.2 U10.T11(RESET_n) U14.E17(DDR_RESETN)
DDR_ZQ: R112.2 U14.G16(DDR_ZQ)
NetR94_1: R94.1 U10.A5(ZQ)

Not connected (* = marked no-connect by the designer): U10 A1(DNU)* A2(DNU)* A8(NC)* A11(DNU)* A12(DNU)* AA1(DNU)* AA2(NC)* AA4(NC)* AA9(NC)* AA11(NC)* AA12(DNU)* AB1(DNU)* AB2(DNU)* AB11(DNU)* AB12(DNU)* B1(DNU)* B12(DNU)* G11(NC)* H3(NC)* J5(NC)* K5(NC)* K8(NC)* N5(NC)* N8(NC)* P2(NC)* P4(NC)* P5(NC)* P8(NC)* P9(NC)* P11(NC)* R2(NC)* R3(NC)* R4(NC)* R9(NC)* R10(NC)* R11(NC)* T2(NC)* U2(NC)* U4(NC)* U9(NC)* U11(NC)* V2(NC)* V3(NC)* V4(NC)* V9(NC)* V10(NC)* V11(NC)* W3(NC)* W10(NC)* Y2(NC)* Y3(NC)* Y4(NC)* Y9(NC)* Y10(NC)* Y11(NC)*; U14 E19(DDR_A20)* F19(DDR_A21)* G17(DDR_A1)* G19(DDR_A22)* H17(DDR_A25)* H19(DDR_A23)* J18(DDR_A13)* K17(DDR_VREF)* K18(DDR_A14)* K19(DDR_A26)* L18(DDR_A15)* L19(DDR_A27)* M18(DDR_A16)* M19(DDR_A28)* N18(DDR_A17)* N19(DDR_A29)* P17(DDR_A7)* P18(DDR_A18)* P19(DDR_A30)* R17(DDR_A12)* R19(DDR_A31)*

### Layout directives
differential pair: DDR_CLK_N, DDR_CLK_P, DDR_DQS0_N, DDR_DQS0_P, DDR_DQS1_N, DDR_DQS1_P

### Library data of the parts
C50 C51 C62 C63 = MCD-01341: Capacitor, MLCC, 10uF, 6V3, X5R, +/-20%, 0603, T=0.8mm; Part_Preference: Recommended; Manufacturer: MURATA; Manufacturer_Part_Number: GRM188R60J106ME47D; Component_Country_Of_Origin: Japan°°; ShowFields: YES; ID: 3441
C52-C61 C64-C68 = MCD-00006: Capacitor, MLCC, 100nF, 16V, X7R, +/-10%, 0402, T=0.5mm; Part_Preference: Recommended; Manufacturer: YAGEO; Manufacturer_Part_Number: CC0402KRX7R7BB104; Partial_Alternate_Internal_Part_Number: MCD-03299; Order_Code_RS: 9402047; Component_Country_Of_Origin: China; ShowFields: YES; ID: 2474
R26 = MCD-00053: Resistor, 10K, 0402, +/-1%, 1/16W; BMS_Part_Number: 9131590; Part_Preference: Recommended; Manufacturer: YAGEO; Manufacturer_Part_Number: RC0402FR-0710KL; Order_Code_RS: 9239359; Component_Country_Of_Origin: China; ShowFields: YES; ID: 2539
R94 R112 = MCD-02253: Resistor, 240R, 0201, +/-1%, 1/20W; Part_Preference: Recommended; Manufacturer: YAGEO; Manufacturer_Part_Number: RC0201FR-07240RL; Component_Country_Of_Origin: China; ShowFields: YES; ID: 4353
U10 = MCD-04012: Memory, SDRAM, 1V1, 16Gbit, 4266MHz; Part_Type: IC; Part_Preference: Recommended; Manufacturer: MICRON; Component_Country_Of_Origin: Taiwan°; ShowFields: YES; ID: 6128
U14 = MCD-03768: as U14 on sheet STM32MP25XXAL I_Os

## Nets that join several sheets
1V8: PMIC (5 pins), STM32MP25XXAL Power (20 pins), eMMC (11 pins)
GND: STM32MP25XXAL I_Os (7 pins), PMIC (62 pins), STM32MP25XXAL Power (94 pins), eMMC (17 pins), LPDDR4_16bits (79 pins)
VDD1_DDR: PMIC (C40.2 U26.44), LPDDR4_16bits (15 pins)
VDD2_DDR: PMIC (5 pins), STM32MP25XXAL Power (12 pins), LPDDR4_16bits (58 pins)
VDD3V3_USB: PMIC (C156.2 U26.13), STM32MP25XXAL Power (R286.1)
VDD_EMMC: PMIC (C190.1 U26.16), eMMC (6 pins)
VDDA1V8_AON: STM32MP25XXAL I_Os (U14.N1), PMIC (C189.2 U26.14), STM32MP25XXAL Power (C234.2 U14.N5)
VDDCORE: PMIC (6 pins), STM32MP25XXAL Power (21 pins)
VDDCPU: PMIC (5 pins), STM32MP25XXAL Power (10 pins)
VDDGPU: PMIC (6 pins), STM32MP25XXAL Power (10 pins)
VDDIO: STM32MP25XXAL I_Os (R27.2 R260.2 R261.2), PMIC (6 pins), STM32MP25XXAL Power (13 pins)
VDDIO_SDCARD: PMIC (C217.1 U26.2), STM32MP25XXAL Power (C210.2 U14.D10)
eMMC.SDMMC2_CK: STM32MP25XXAL I_Os (U14.G14), eMMC (R103.1 U37.M6)
eMMC.SDMMC2_CMD: STM32MP25XXAL I_Os (U14.D14), eMMC (R104.1 U37.M5)
eMMC.SDMMC2_D0: STM32MP25XXAL I_Os (U14.A16), eMMC (R101.1 U37.A3)
eMMC.SDMMC2_D1: STM32MP25XXAL I_Os (U14.B16), eMMC (U37.A4)
eMMC.SDMMC2_D2: STM32MP25XXAL I_Os (U14.B15), eMMC (U37.A5)
eMMC.SDMMC2_D3: STM32MP25XXAL I_Os (U14.C16), eMMC (U37.B2)
eMMC.SDMMC2_D4: STM32MP25XXAL I_Os (U14.D15), eMMC (U37.B3)
eMMC.SDMMC2_D5: STM32MP25XXAL I_Os (U14.F15), eMMC (U37.B4)
eMMC.SDMMC2_D6: STM32MP25XXAL I_Os (U14.F14), eMMC (U37.B5)
eMMC.SDMMC2_D7: STM32MP25XXAL I_Os (U14.C15), eMMC (U37.B6)
I2C7.SCL: STM32MP25XXAL I_Os (R261.1 U14.A11), PMIC (U26.33)
I2C7.SDA: STM32MP25XXAL I_Os (R260.1 U14.A13), PMIC (U26.34)
MP257_WAKEUP: STM32MP25XXAL I_Os (U14.P15), PMIC (U26.32)
NRST: STM32MP25XXAL I_Os (C33.2 U14.N2), PMIC (R81.1)
NRSTC1MS: STM32MP25XXAL I_Os (R27.1 R272.1 U14.T1), PMIC (R59.1), eMMC (D7.2)
PMIC_WAKEUPn: STM32MP25XXAL I_Os (U14.P4), PMIC (R46.1)
PWR_CPU_ON: STM32MP25XXAL I_Os (R272.2 U14.P2), PMIC (R60.1)
PWR_ON: STM32MP25XXAL I_Os (U14.U3), PMIC (R2.1)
